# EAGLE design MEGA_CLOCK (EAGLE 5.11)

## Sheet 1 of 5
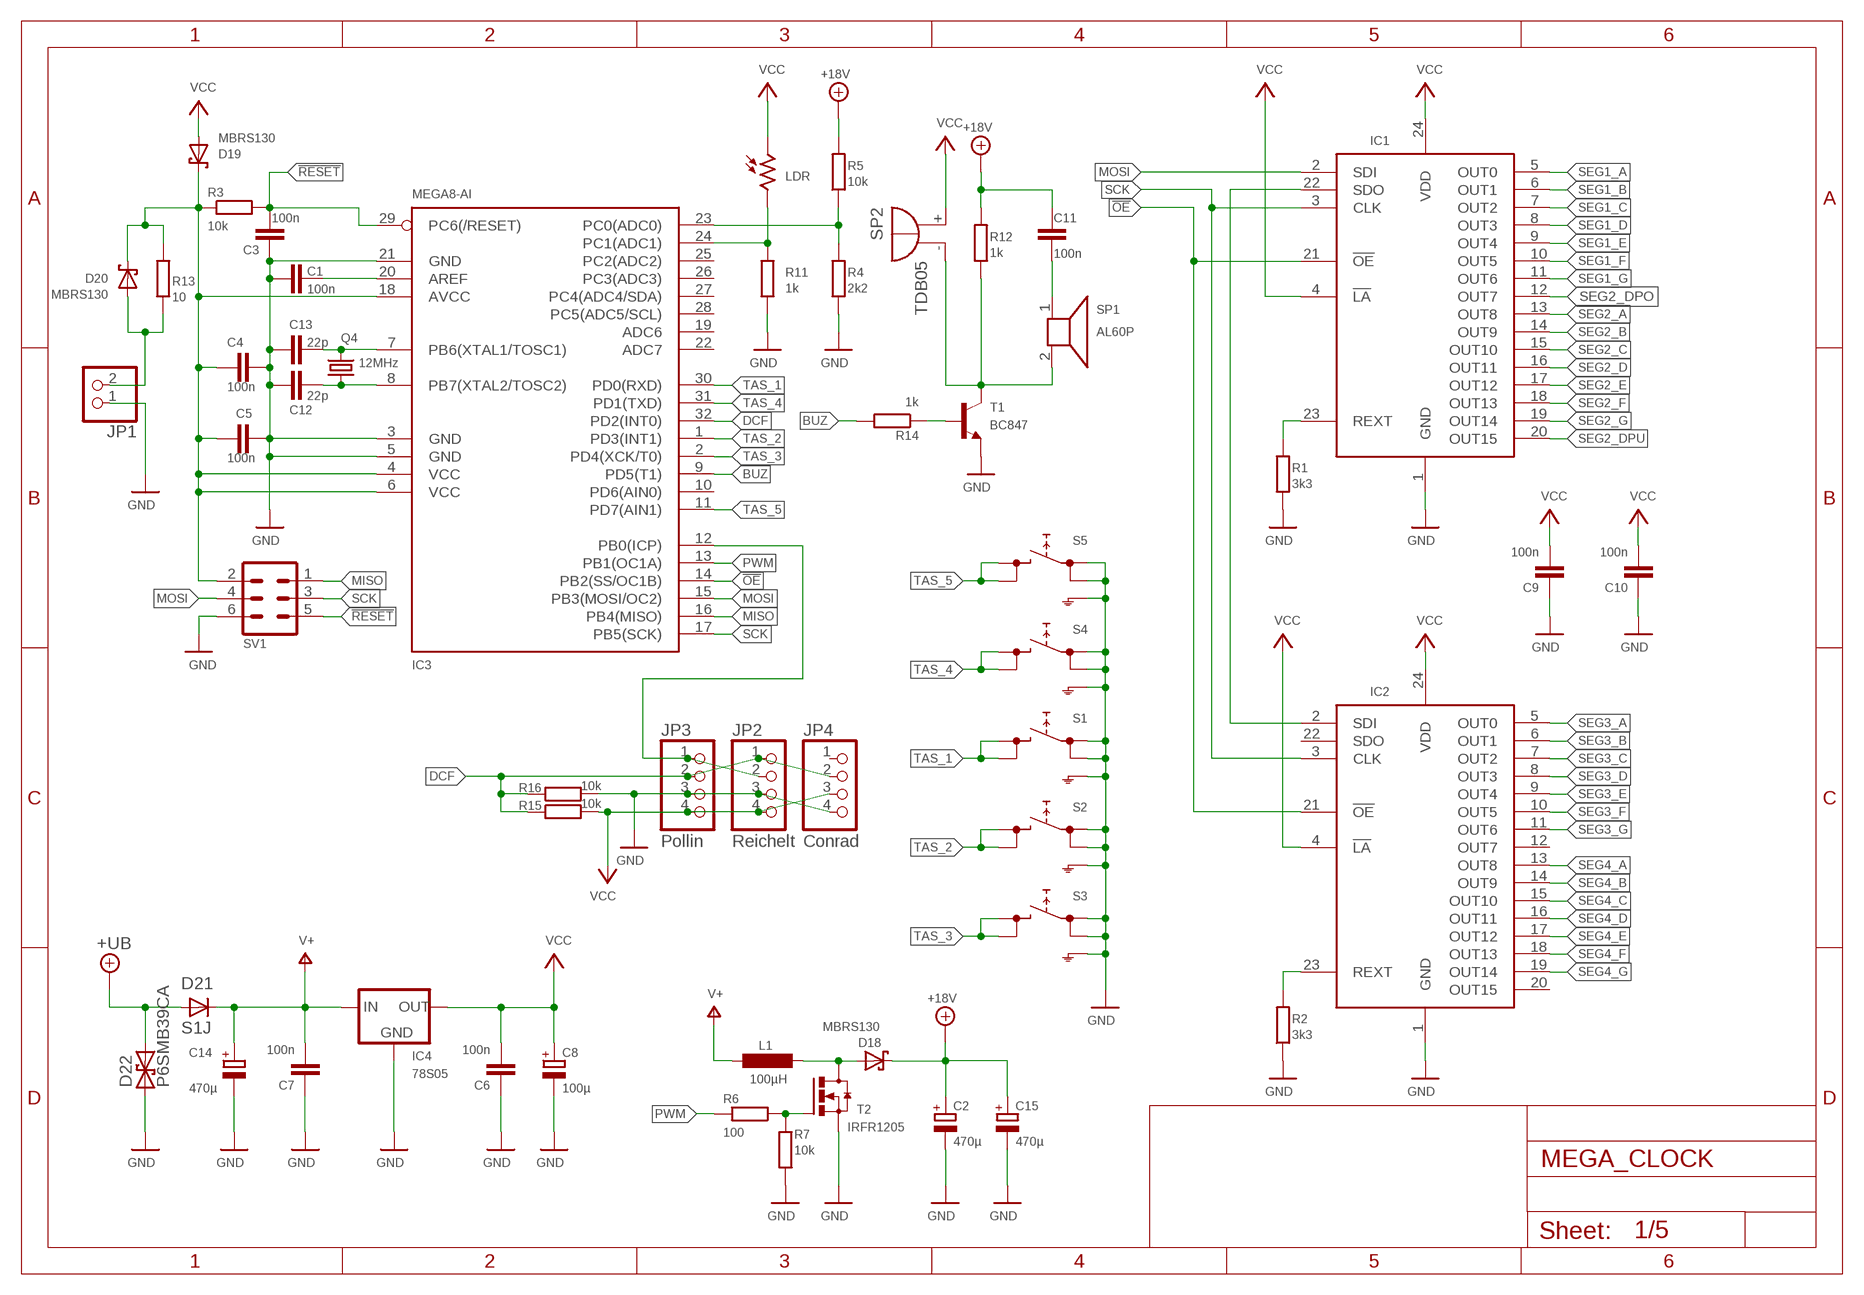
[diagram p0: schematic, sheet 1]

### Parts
C1  100n  C-EUC0805  [C0805]
C2  470µ  CPOL-EUE5-10.5  [E5-10,5]
C3  100n  C-EUC0805  [C0805]
C4  100n  C-EUC0805  [C0805]
C5  100n  C-EUC0805  [C0805]
C6  100n  C-EUC0805  [C0805]
C7  100n  C-EUC0805  [C0805]
C8  100µ  CPOL-EUSMCD  [SMC_D]
C9  100n  C-EUC0805  [C0805]
C10  100n  C-EUC0805  [C0805]
C11  100n  C-EUC0805  [C0805]
C12  22p  C-EUC0805  [C0805]
C13  22p  C-EUC0805  [C0805]
C14  470µ  CPOL-EUE5-10.5  [E5-10,5]
C15  470µ  CPOL-EUE5-10.5  [E5-10,5]
D18  MBRS130  MBRS130LT3  [SMB]
D19  MBRS130  MBRS130LT3  [SMB]
D20  MBRS130  MBRS130LT3  [SMB]
D21  S1J  GF1  [SMA-DO214AC]
D22  P6SMB39CA  [DO214AC-BI]
IC1  SCT24  [SSOP24]
IC2  SCT24  [SSOP24]
IC3  MEGA8-AI  [TQFP32-08]
IC4  78S05  78XXS  [78XXS]
JP1  PINHD-1X2  [1X02]
JP2  Reichelt  PINHD-1X4/90  [1X04/90]
JP3  Pollin  PINHD-1X4/90  [1X04/90]
JP4  Conrad  PINHD-1X4/90  [1X04/90]
L1  100µH  DO3316P  [DO3316P]
LDR  A1050_09  [T0-46-A10XX]
Q4  12MHz  CRYSTALCTS406  [CTS406]
R1  3k3  R-EU_R0805  [R0805]
R2  3k3  R-EU_R0805  [R0805]
R3  10k  R-EU_R0805  [R0805]
R4  2k2  R-EU_R0805  [R0805]
R5  10k  R-EU_R0805  [R0805]
R6  100  R-EU_R0805  [R0805]
R7  10k  R-EU_R0805  [R0805]
R11  1k  R-EU_R0805  [R0805]
R12  1k  R-EU_R0805  [R0805]
R13  10  R-EU_R0805  [R0805]
R14  1k  R-EU_R0805  [R0805]
R15  10k  R-EU_R0805  [R0805]
R16  10k  R-EU_R0805  [R0805]
S1  SKHMPWE010  [SKHMPXE010]
S2  SKHMPWE010  [SKHMPXE010]
S3  SKHMPWE010  [SKHMPXE010]
S4  SKHMPWE010  [SKHMPXE010]
S5  SKHMPWE010  [SKHMPXE010]
SP1  AL60P  [AL60P]
SP2  TDB05  BMT1205XH7.5  [BMT1205XH7.5]
SV1  ML6  [ML6]
T1  BC847  [SOT23]
T2  IRFR1205  [D-PAK_TO252AA]

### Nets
!OE: IC1.21(!OE) IC2.21(!OE) IC3.14(PB2(SS/OC1B))
!RESET: C3.2 IC3.29(PC6(/RESET)) R3.2 SV1.5
+12V: C2.+ C11.2 C15.+ D18.C R5.2 R12.2 ; supply symbol labelled +18V ; also sheet 2,3,4,5
+UB: D21.A D22.2
BUZ: IC3.9(PD5(T1)) R14.2
DCF: IC3.32(PD2(INT0)) JP2.1 JP3.2 JP4.2 R15.1 R16.1
GND: C1.1 C2.- C3.1 C4.2 C5.2 C6.1 C7.1 C8.- C9.1 C10.1 C12.1 C13.1 C14.- C15.- D22.1 IC1.1(GND) IC2.1(GND) IC3.3(GND) IC3.5(GND) IC3.21(GND) IC4.GND JP1.1 JP2.3 JP3.3 JP4.4 R1.1 R2.1 R4.1 R7.2 R11.1 R16.2 S1.1(1.1) S1.2(1.2) S1.5(SH) S2.1(1.1) S2.2(1.2) S2.5(SH) S3.1(1.1) S3.2(1.2) S3.5(SH) S4.1(1.1) S4.2(1.2) S4.5(SH) S5.1(1.1) S5.2(1.2) S5.5(SH) SV1.6 T1.2(E) T2.3(S)
MISO: IC3.16(PB4(MISO)) SV1.1
MOSI: IC1.2(SDI) IC3.15(PB3(MOSI/OC2)) SV1.4
N$2: IC2.23(REXT) R2.2
N$3: IC1.23(REXT) R1.2
N$5: C1.2 IC3.20(AREF)
N$6: IC3.23(PC0(ADC0)) R4.2 R5.1
N$7: C13.2 IC3.7(PB6(XTAL1/TOSC1)) Q4.3
N$8: C12.2 IC3.8(PB7(XTAL2/TOSC2)) Q4.1
N$9: D18.A L1.2 T2.4(D)
N$10: IC3.24(PC1(ADC1)) LDR.2 R11.2
N$11: R6.1 R7.1 T2.1(G)
N$13: R12.1 SP1.2 SP2.- T1.3(C)
N$31: C11.1 SP1.1
N$36: D20.A JP1.2 R13.1
N$41: R14.1 T1.1(B)
N$46: C4.1 C5.1 D19.C D20.C IC3.4(VCC) IC3.6(VCC) IC3.18(AVCC) R3.1 R13.2 SV1.2
N$83: IC3.12(PB0(ICP)) JP2.2 JP3.1
N$101: IC1.22(SDO) IC2.2(SDI)
PWM: IC3.13(PB1(OC1A)) R6.2
SCK: IC1.3(CLK) IC2.3(CLK) IC3.17(PB5(SCK)) SV1.3
SEG1_A: IC1.5(OUT0) ; also sheet 2
SEG1_B: IC1.6(OUT1) ; also sheet 2
SEG1_C: IC1.7(OUT2) ; also sheet 2
SEG1_D: IC1.8(OUT3) ; also sheet 2
SEG1_E: IC1.9(OUT4) ; also sheet 2
SEG1_F: IC1.10(OUT5) ; also sheet 2
SEG1_G: IC1.11(OUT6) ; also sheet 2
SEG2_A: IC1.13(OUT8) ; also sheet 3
SEG2_B: IC1.14(OUT9) ; also sheet 3
SEG2_C: IC1.15(OUT10) ; also sheet 3
SEG2_D: IC1.16(OUT11) ; also sheet 3
SEG2_DPO: IC1.12(OUT7) ; also sheet 3
SEG2_DPU: IC1.20(OUT15) ; also sheet 3
SEG2_E: IC1.17(OUT12) ; also sheet 3
SEG2_F: IC1.18(OUT13) ; also sheet 3
SEG2_G: IC1.19(OUT14) ; also sheet 3
SEG3_A: IC2.5(OUT0) ; also sheet 4
SEG3_B: IC2.6(OUT1) ; also sheet 4
SEG3_C: IC2.7(OUT2) ; also sheet 4
SEG3_D: IC2.8(OUT3) ; also sheet 4
SEG3_E: IC2.9(OUT4) ; also sheet 4
SEG3_F: IC2.10(OUT5) ; also sheet 4
SEG3_G: IC2.11(OUT6) ; also sheet 4
SEG4_A: IC2.13(OUT8) ; also sheet 5
SEG4_B: IC2.14(OUT9) ; also sheet 5
SEG4_C: IC2.15(OUT10) ; also sheet 5
SEG4_D: IC2.16(OUT11) ; also sheet 5
SEG4_E: IC2.17(OUT12) ; also sheet 5
SEG4_F: IC2.18(OUT13) ; also sheet 5
SEG4_G: IC2.19(OUT14) ; also sheet 5
TAS_1: IC3.30(PD0(RXD)) S1.3(2.1) S1.4(2.2)
TAS_2: IC3.1(PD3(INT1)) S2.3(2.1) S2.4(2.2)
TAS_3: IC3.2(PD4(XCK/T0)) S3.3(2.1) S3.4(2.2)
TAS_4: IC3.31(PD1(TXD)) S4.3(2.1) S4.4(2.2)
TAS_5: IC3.11(PD7(AIN1)) S5.3(2.1) S5.4(2.2)
V+: C7.2 C14.+ D21.K(C) IC4.IN L1.1
VCC: C6.2 C8.+ C9.2 C10.2 D19.A IC1.4(!LA) IC1.24(VDD) IC2.4(!LA) IC2.24(VDD) IC4.OUT JP2.4 JP3.4 JP4.3 LDR.1 R15.2 SP2.+
Unconnected: IC2.12(OUT7) IC2.20(OUT15) IC2.22(SDO) IC3.10(PD6(AIN0)) IC3.19(ADC6) IC3.22(ADC7) IC3.25(PC2(ADC2)) IC3.26(PC3(ADC3)) IC3.27(PC4(ADC4/SDA)) IC3.28(PC5(ADC5/SCL)) JP4.1

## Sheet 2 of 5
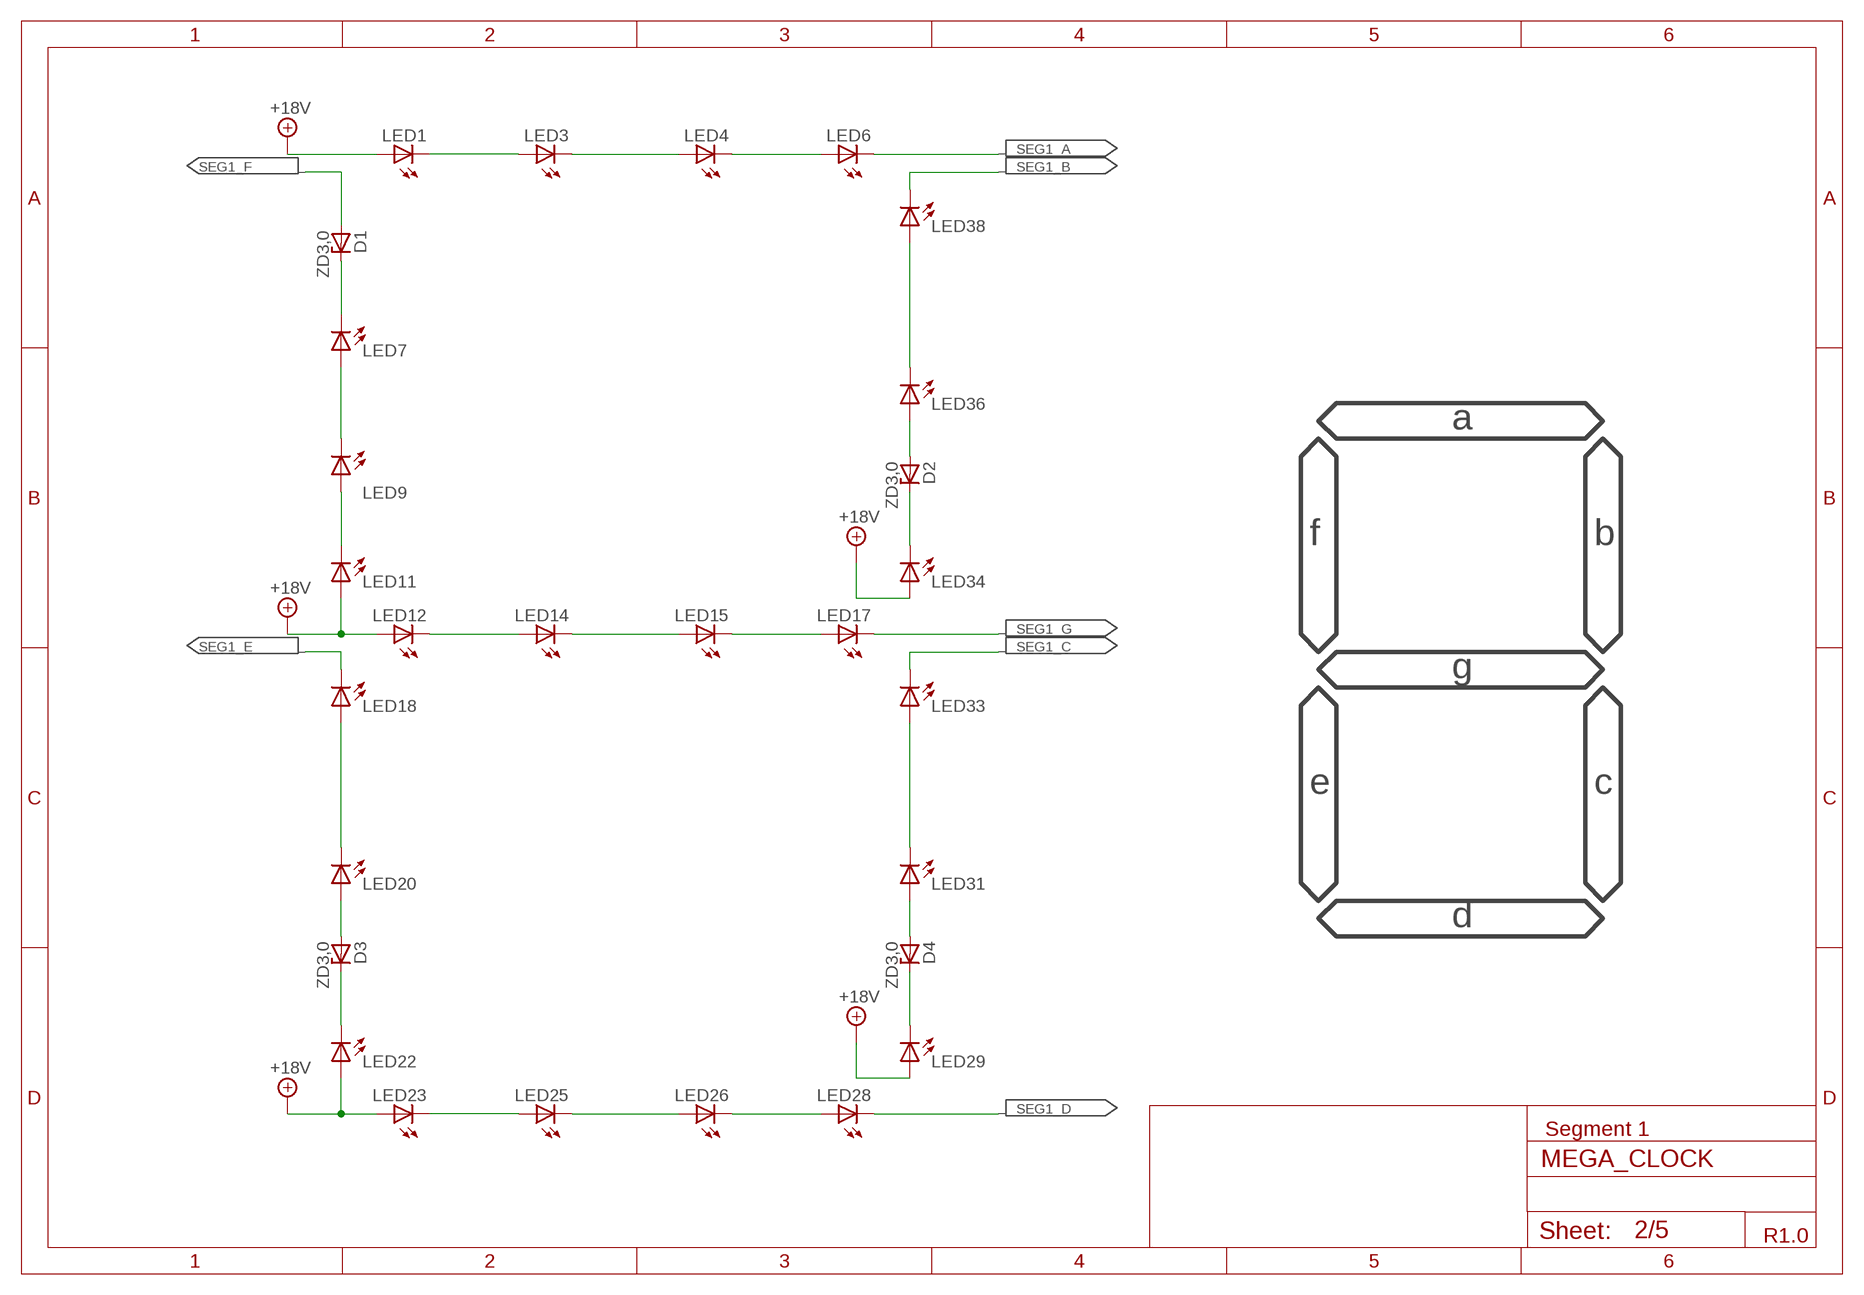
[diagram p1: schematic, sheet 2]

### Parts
D1  ZD3,0  ZENER-DIODESOD80C  [SOD80C]
D2  ZD3,0  ZENER-DIODESOD80C  [SOD80C]
D3  ZD3,0  ZENER-DIODESOD80C  [SOD80C]
D4  ZD3,0  ZENER-DIODESOD80C  [SOD80C]
LED1  LEDP-LCC-2  [P-LCC-2]
LED3  LEDP-LCC-2  [P-LCC-2]
LED4  LEDP-LCC-2  [P-LCC-2]
LED6  LEDP-LCC-2  [P-LCC-2]
LED7  LEDP-LCC-2  [P-LCC-2]
LED9  LEDP-LCC-2  [P-LCC-2]
LED11  LEDP-LCC-2  [P-LCC-2]
LED12  LEDP-LCC-2  [P-LCC-2]
LED14  LEDP-LCC-2  [P-LCC-2]
LED15  LEDP-LCC-2  [P-LCC-2]
LED17  LEDP-LCC-2  [P-LCC-2]
LED18  LEDP-LCC-2  [P-LCC-2]
LED20  LEDP-LCC-2  [P-LCC-2]
LED22  LEDP-LCC-2  [P-LCC-2]
LED23  LEDP-LCC-2  [P-LCC-2]
LED25  LEDP-LCC-2  [P-LCC-2]
LED26  LEDP-LCC-2  [P-LCC-2]
LED28  LEDP-LCC-2  [P-LCC-2]
LED29  LEDP-LCC-2  [P-LCC-2]
LED31  LEDP-LCC-2  [P-LCC-2]
LED33  LEDP-LCC-2  [P-LCC-2]
LED34  LEDP-LCC-2  [P-LCC-2]
LED36  LEDP-LCC-2  [P-LCC-2]
LED38  LEDP-LCC-2  [P-LCC-2]

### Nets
+12V: LED1.A LED11.A LED12.A LED22.A LED23.A LED29.A LED34.A ; supply symbol labelled +18V ; also sheet 1,3,4,5
N$14: LED18.A LED20.C
N$15: LED23.C LED25.A
N$16: LED3.C LED4.A
N$17: LED26.C LED28.A
N$18: LED15.C LED17.A
N$19: LED12.C LED14.A
N$20: LED1.C LED3.A
N$21: LED14.C LED15.A
N$22: LED4.C LED6.A
N$23: LED7.A LED9.C
N$24: D3.A LED20.A
N$25: LED36.C LED38.A
N$26: LED25.C LED26.A
N$27: D3.C LED22.C
N$28: LED31.C LED33.A
N$39: D4.C LED29.C
N$44: D4.A LED31.A
N$76: D1.C LED7.C
N$82: LED9.A LED11.C
N$107: D2.C LED34.C
N$108: D2.A LED36.A
SEG1_A: LED6.C ; also sheet 1
SEG1_B: LED38.C ; also sheet 1
SEG1_C: LED33.C ; also sheet 1
SEG1_D: LED28.C ; also sheet 1
SEG1_E: LED18.C ; also sheet 1
SEG1_F: D1.A ; also sheet 1
SEG1_G: LED17.C ; also sheet 1

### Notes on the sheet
- a
- f | b
- g
- e | c
- d
- Segment 1
- R1.0

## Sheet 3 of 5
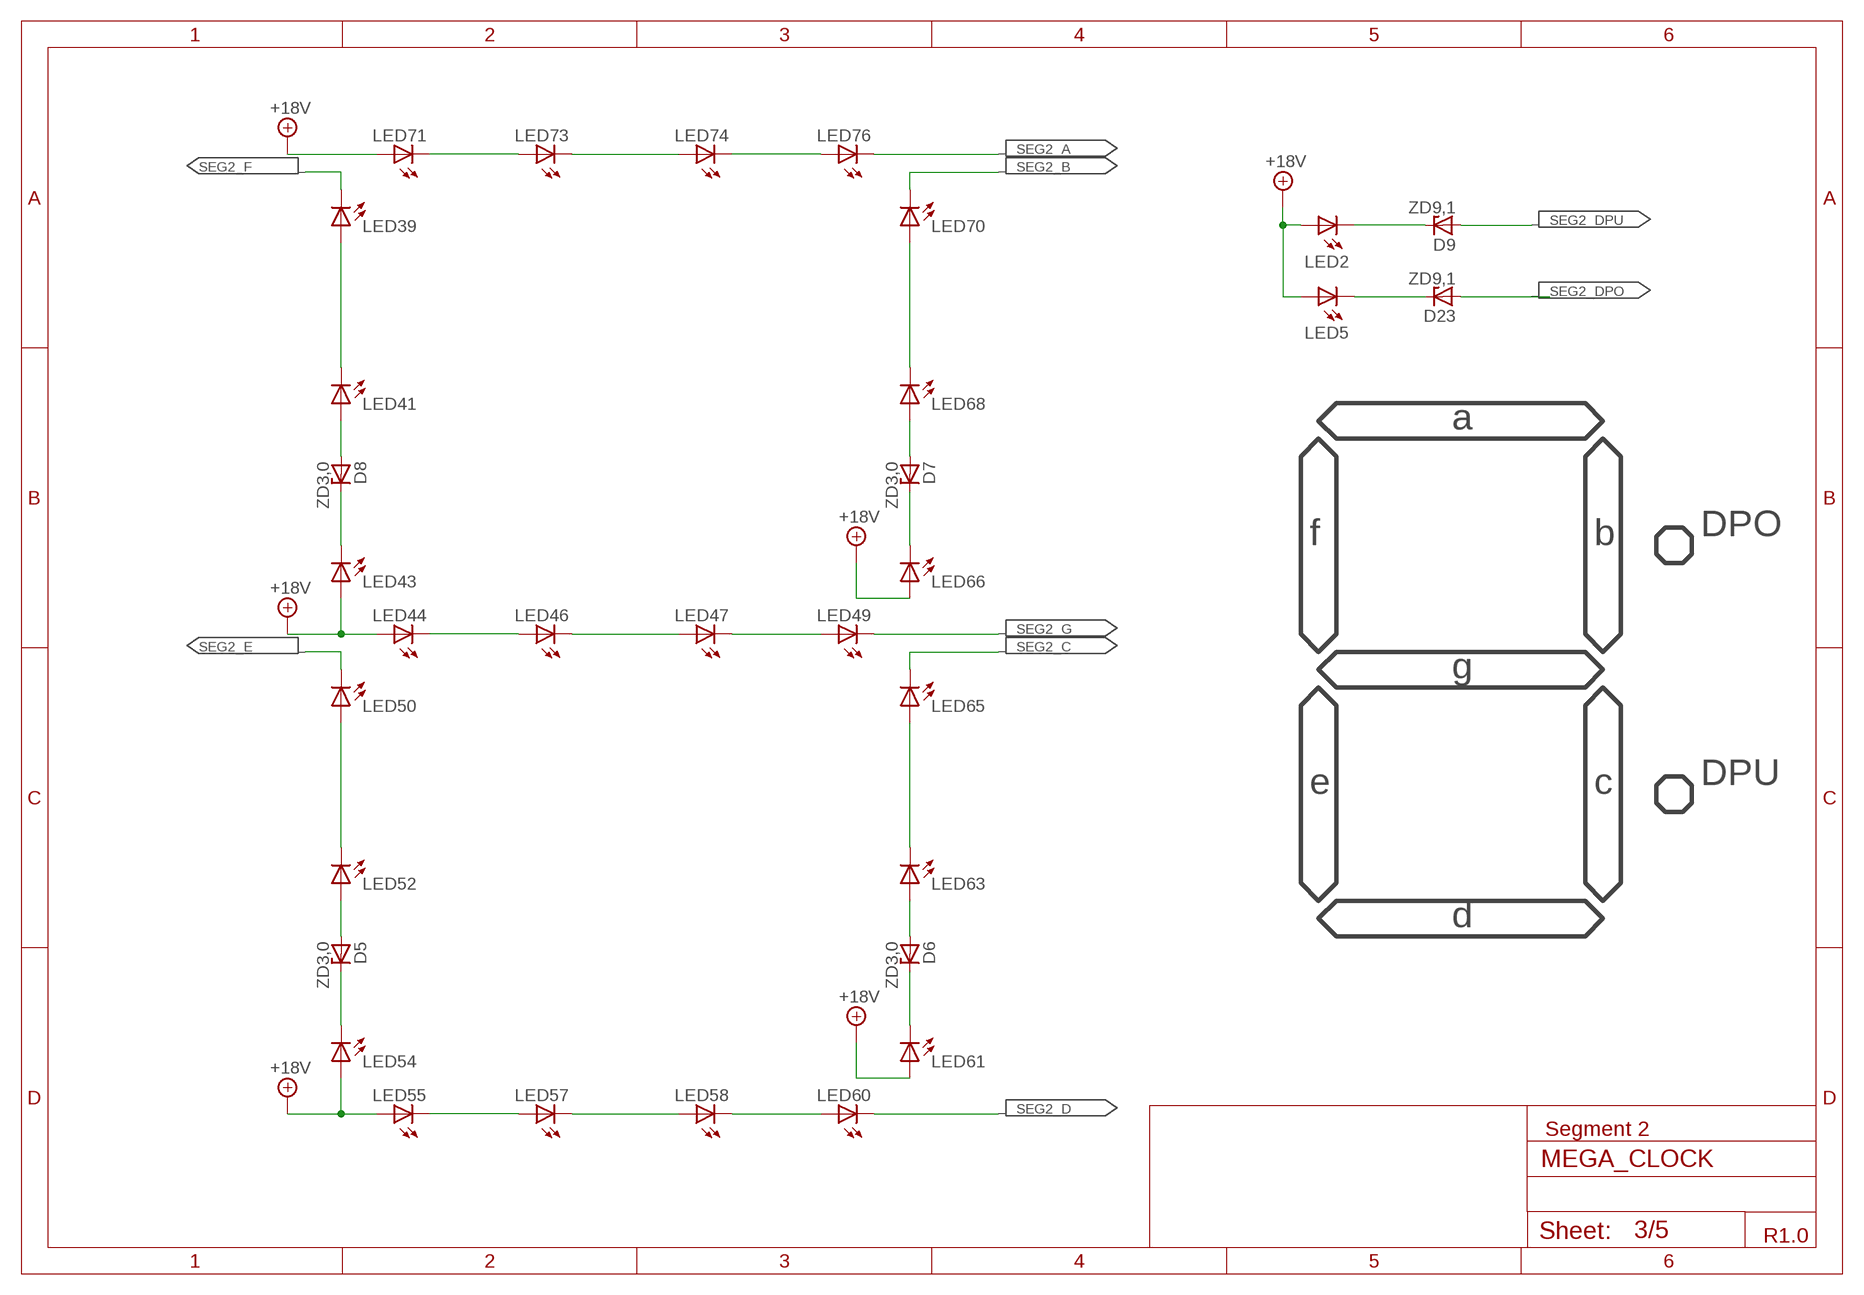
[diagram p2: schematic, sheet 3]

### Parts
D5  ZD3,0  ZENER-DIODESOD80C  [SOD80C]
D6  ZD3,0  ZENER-DIODESOD80C  [SOD80C]
D7  ZD3,0  ZENER-DIODESOD80C  [SOD80C]
D8  ZD3,0  ZENER-DIODESOD80C  [SOD80C]
D9  ZD9,1  ZENER-DIODESOD80C  [SOD80C]
D23  ZD9,1  ZENER-DIODESOD80C  [SOD80C]
LED2  LEDP-LCC-2  [P-LCC-2]
LED5  LEDP-LCC-2  [P-LCC-2]
LED39  LEDP-LCC-2  [P-LCC-2]
LED41  LEDP-LCC-2  [P-LCC-2]
LED43  LEDP-LCC-2  [P-LCC-2]
LED44  LEDP-LCC-2  [P-LCC-2]
LED46  LEDP-LCC-2  [P-LCC-2]
LED47  LEDP-LCC-2  [P-LCC-2]
LED49  LEDP-LCC-2  [P-LCC-2]
LED50  LEDP-LCC-2  [P-LCC-2]
LED52  LEDP-LCC-2  [P-LCC-2]
LED54  LEDP-LCC-2  [P-LCC-2]
LED55  LEDP-LCC-2  [P-LCC-2]
LED57  LEDP-LCC-2  [P-LCC-2]
LED58  LEDP-LCC-2  [P-LCC-2]
LED60  LEDP-LCC-2  [P-LCC-2]
LED61  LEDP-LCC-2  [P-LCC-2]
LED63  LEDP-LCC-2  [P-LCC-2]
LED65  LEDP-LCC-2  [P-LCC-2]
LED66  LEDP-LCC-2  [P-LCC-2]
LED68  LEDP-LCC-2  [P-LCC-2]
LED70  LEDP-LCC-2  [P-LCC-2]
LED71  LEDP-LCC-2  [P-LCC-2]
LED73  LEDP-LCC-2  [P-LCC-2]
LED74  LEDP-LCC-2  [P-LCC-2]
LED76  LEDP-LCC-2  [P-LCC-2]

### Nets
+12V: LED2.A LED5.A LED43.A LED44.A LED54.A LED55.A LED61.A LED66.A LED71.A ; supply symbol labelled +18V ; also sheet 1,2,4,5
N$1: D23.C LED5.C
N$29: LED39.A LED41.C
N$30: LED68.C LED70.A
N$32: LED74.C LED76.A
N$33: LED71.C LED73.A
N$34: LED47.C LED49.A
N$35: LED44.C LED46.A
N$37: D9.C LED2.C
N$38: D5.A LED52.A
N$40: LED58.C LED60.A
N$42: LED55.C LED57.A
N$43: D5.C LED54.C
N$45: D6.C LED61.C
N$47: LED50.A LED52.C
N$48: LED63.C LED65.A
N$51: LED73.C LED74.A
N$56: LED46.C LED47.A
N$61: LED57.C LED58.A
N$111: D6.A LED63.A
N$112: D8.A LED41.A
N$113: D8.C LED43.C
N$114: D7.C LED66.C
N$115: D7.A LED68.A
SEG2_A: LED76.C ; also sheet 1
SEG2_B: LED70.C ; also sheet 1
SEG2_C: LED65.C ; also sheet 1
SEG2_D: LED60.C ; also sheet 1
SEG2_DPO: D23.A ; also sheet 1
SEG2_DPU: D9.A ; also sheet 1
SEG2_E: LED50.C ; also sheet 1
SEG2_F: LED39.C ; also sheet 1
SEG2_G: LED49.C ; also sheet 1

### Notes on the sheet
- a
- f | b | DPO
- g
- e | c | DPU
- d
- Segment 2
- R1.0

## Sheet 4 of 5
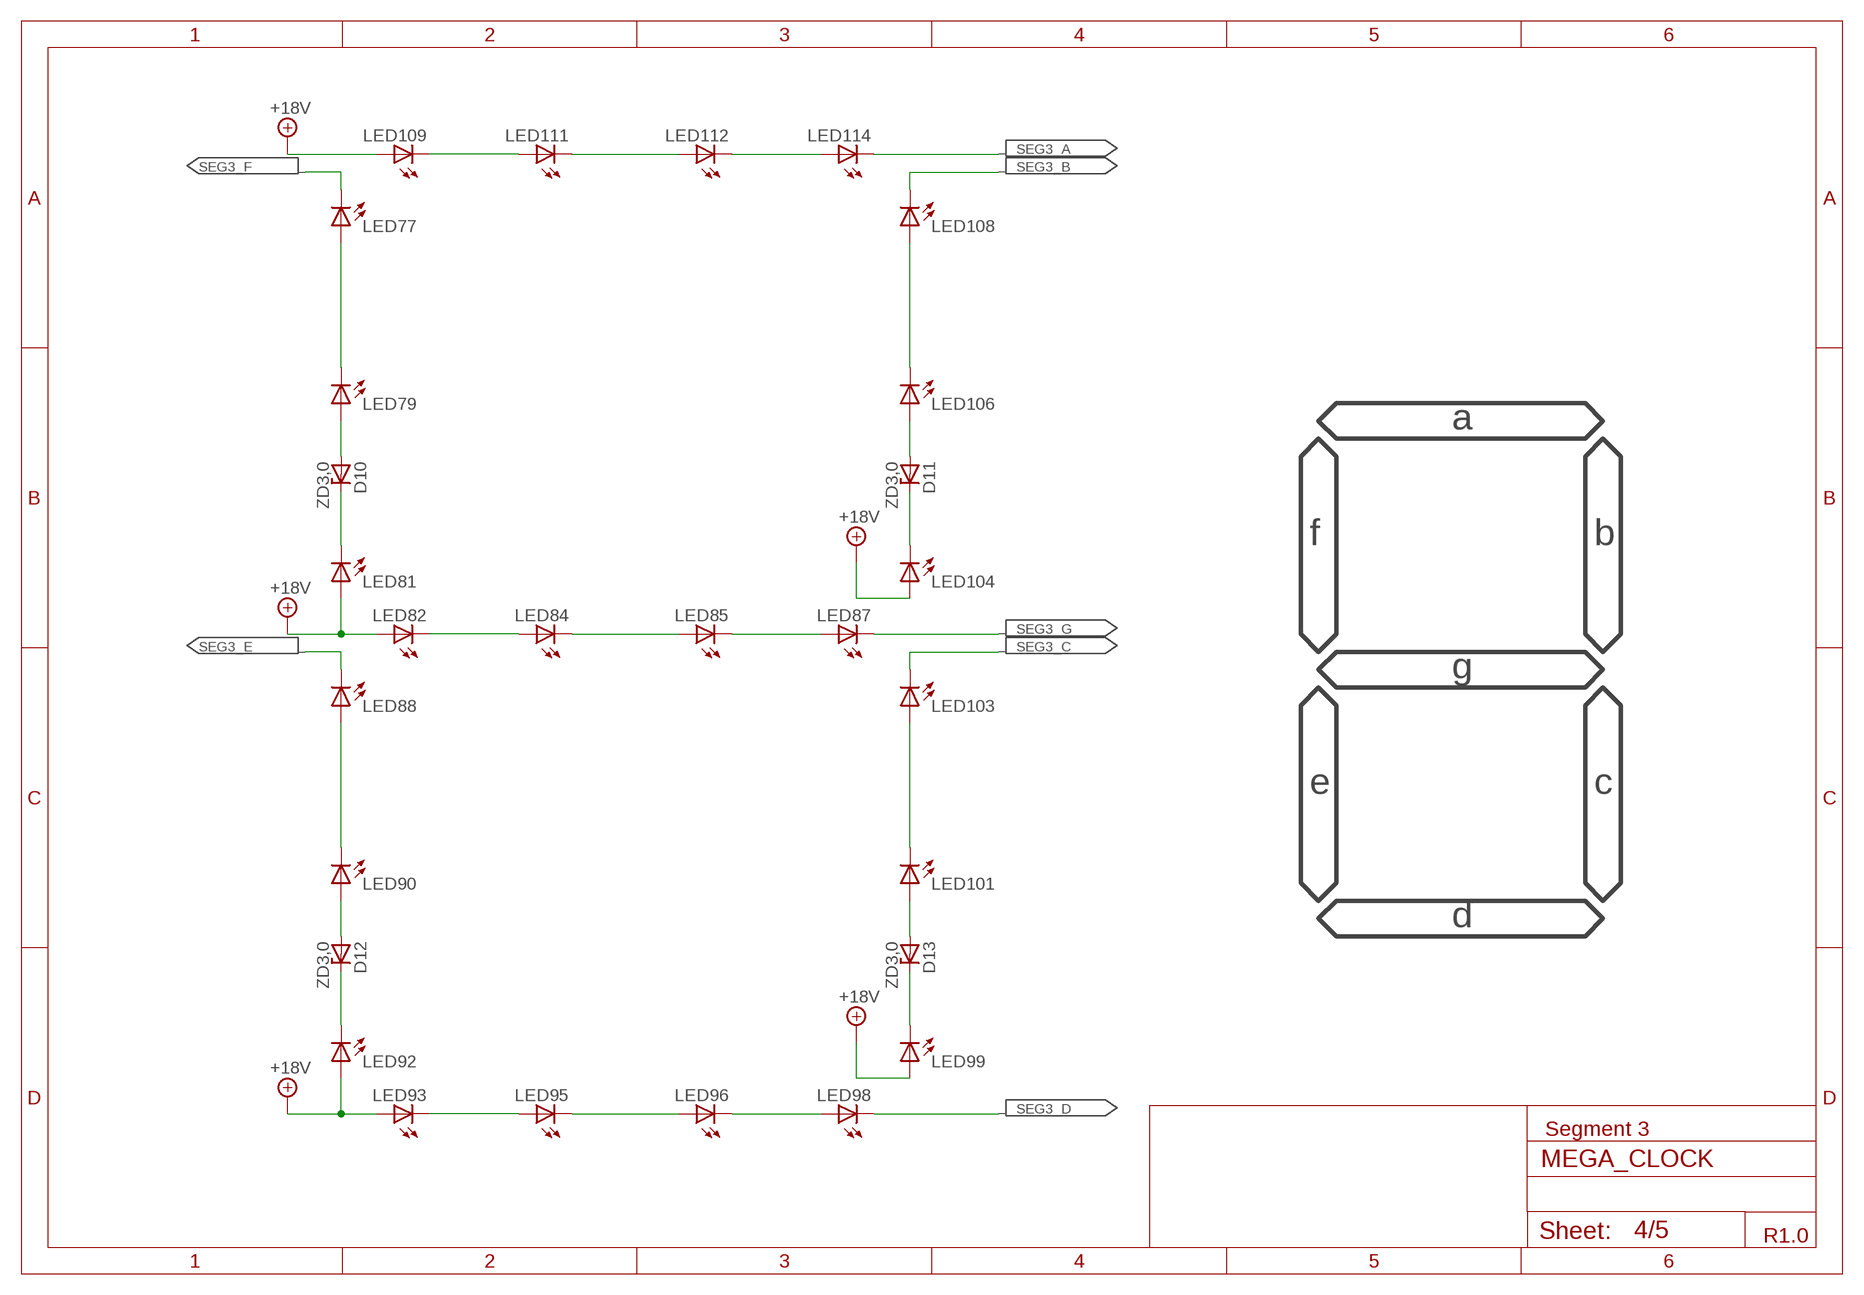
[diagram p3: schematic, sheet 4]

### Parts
D10  ZD3,0  ZENER-DIODESOD80C  [SOD80C]
D11  ZD3,0  ZENER-DIODESOD80C  [SOD80C]
D12  ZD3,0  ZENER-DIODESOD80C  [SOD80C]
D13  ZD3,0  ZENER-DIODESOD80C  [SOD80C]
LED77  LEDP-LCC-2  [P-LCC-2]
LED79  LEDP-LCC-2  [P-LCC-2]
LED81  LEDP-LCC-2  [P-LCC-2]
LED82  LEDP-LCC-2  [P-LCC-2]
LED84  LEDP-LCC-2  [P-LCC-2]
LED85  LEDP-LCC-2  [P-LCC-2]
LED87  LEDP-LCC-2  [P-LCC-2]
LED88  LEDP-LCC-2  [P-LCC-2]
LED90  LEDP-LCC-2  [P-LCC-2]
LED92  LEDP-LCC-2  [P-LCC-2]
LED93  LEDP-LCC-2  [P-LCC-2]
LED95  LEDP-LCC-2  [P-LCC-2]
LED96  LEDP-LCC-2  [P-LCC-2]
LED98  LEDP-LCC-2  [P-LCC-2]
LED99  LEDP-LCC-2  [P-LCC-2]
LED101  LEDP-LCC-2  [P-LCC-2]
LED103  LEDP-LCC-2  [P-LCC-2]
LED104  LEDP-LCC-2  [P-LCC-2]
LED106  LEDP-LCC-2  [P-LCC-2]
LED108  LEDP-LCC-2  [P-LCC-2]
LED109  LEDP-LCC-2  [P-LCC-2]
LED111  LEDP-LCC-2  [P-LCC-2]
LED112  LEDP-LCC-2  [P-LCC-2]
LED114  LEDP-LCC-2  [P-LCC-2]

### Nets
+12V: LED81.A LED82.A LED92.A LED93.A LED99.A LED104.A LED109.A ; supply symbol labelled +18V ; also sheet 1,2,3,5
N$49: LED96.C LED98.A
N$50: LED93.C LED95.A
N$52: D10.C LED81.C
N$53: D10.A LED79.A
N$54: LED85.C LED87.A
N$55: LED82.C LED84.A
N$57: LED88.A LED90.C
N$58: LED101.C LED103.A
N$59: LED109.C LED111.A
N$60: LED112.C LED114.A
N$62: LED77.A LED79.C
N$63: LED106.C LED108.A
N$86: LED111.C LED112.A
N$91: LED84.C LED85.A
N$96: LED95.C LED96.A
N$99: D11.A LED106.A
N$104: D11.C LED104.C
N$116: D13.A LED101.A
N$117: D13.C LED99.C
N$118: D12.A LED90.A
N$119: D12.C LED92.C
SEG3_A: LED114.C ; also sheet 1
SEG3_B: LED108.C ; also sheet 1
SEG3_C: LED103.C ; also sheet 1
SEG3_D: LED98.C ; also sheet 1
SEG3_E: LED88.C ; also sheet 1
SEG3_F: LED77.C ; also sheet 1
SEG3_G: LED87.C ; also sheet 1

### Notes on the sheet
- a
- f | b
- g
- e | c
- d
- Segment 3
- R1.0

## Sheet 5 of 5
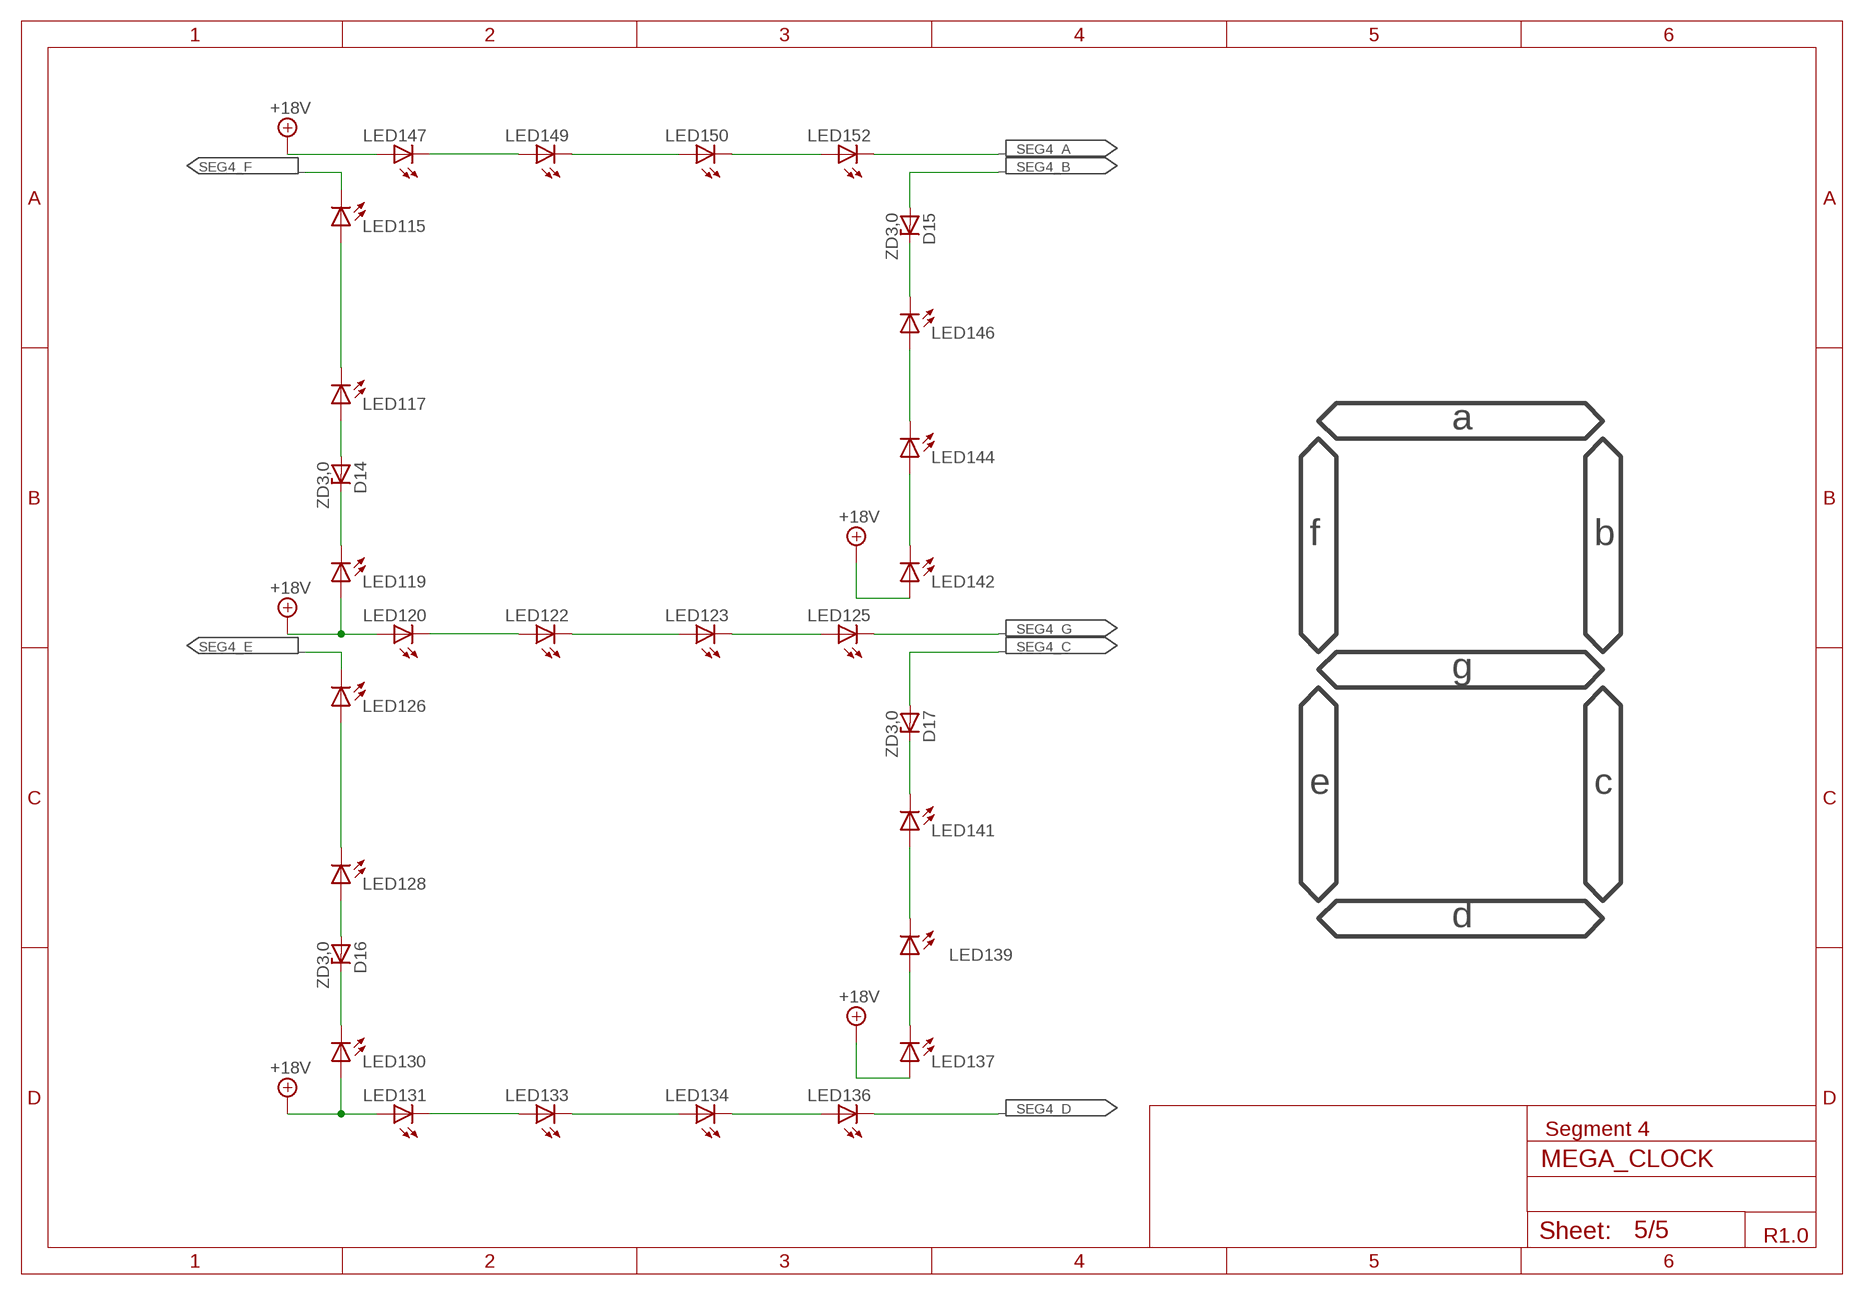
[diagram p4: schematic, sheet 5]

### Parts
D14  ZD3,0  ZENER-DIODESOD80C  [SOD80C]
D15  ZD3,0  ZENER-DIODESOD80C  [SOD80C]
D16  ZD3,0  ZENER-DIODESOD80C  [SOD80C]
D17  ZD3,0  ZENER-DIODESOD80C  [SOD80C]
LED115  LEDP-LCC-2  [P-LCC-2]
LED117  LEDP-LCC-2  [P-LCC-2]
LED119  LEDP-LCC-2  [P-LCC-2]
LED120  LEDP-LCC-2  [P-LCC-2]
LED122  LEDP-LCC-2  [P-LCC-2]
LED123  LEDP-LCC-2  [P-LCC-2]
LED125  LEDP-LCC-2  [P-LCC-2]
LED126  LEDP-LCC-2  [P-LCC-2]
LED128  LEDP-LCC-2  [P-LCC-2]
LED130  LEDP-LCC-2  [P-LCC-2]
LED131  LEDP-LCC-2  [P-LCC-2]
LED133  LEDP-LCC-2  [P-LCC-2]
LED134  LEDP-LCC-2  [P-LCC-2]
LED136  LEDP-LCC-2  [P-LCC-2]
LED137  LEDP-LCC-2  [P-LCC-2]
LED139  LEDP-LCC-2  [P-LCC-2]
LED141  LEDP-LCC-2  [P-LCC-2]
LED142  LEDP-LCC-2  [P-LCC-2]
LED144  LEDP-LCC-2  [P-LCC-2]
LED146  LEDP-LCC-2  [P-LCC-2]
LED147  LEDP-LCC-2  [P-LCC-2]
LED149  LEDP-LCC-2  [P-LCC-2]
LED150  LEDP-LCC-2  [P-LCC-2]
LED152  LEDP-LCC-2  [P-LCC-2]

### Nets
+12V: LED119.A LED120.A LED130.A LED131.A LED137.A LED142.A LED147.A ; supply symbol labelled +18V ; also sheet 1,2,3,4
N$12: LED142.C LED144.A
N$64: LED134.C LED136.A
N$65: LED131.C LED133.A
N$66: D15.C LED146.C
N$67: D14.A LED117.A
N$68: LED139.C LED141.A
N$69: D14.C LED119.C
N$70: LED126.A LED128.C
N$71: LED137.C LED139.A
N$72: D17.C LED141.C
N$74: LED150.C LED152.A
N$75: LED147.C LED149.A
N$77: LED115.A LED117.C
N$78: LED144.C LED146.A
N$79: LED123.C LED125.A
N$80: LED120.C LED122.A
N$120: D16.A LED128.A
N$121: LED149.C LED150.A
N$122: D16.C LED130.C
N$126: LED122.C LED123.A
N$131: LED133.C LED134.A
SEG4_A: LED152.C ; also sheet 1
SEG4_B: D15.A ; also sheet 1
SEG4_C: D17.A ; also sheet 1
SEG4_D: LED136.C ; also sheet 1
SEG4_E: LED126.C ; also sheet 1
SEG4_F: LED115.C ; also sheet 1
SEG4_G: LED125.C ; also sheet 1

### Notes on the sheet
- a
- f | b
- g
- e | c
- d
- Segment 4
- R1.0

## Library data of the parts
C1 C3-C7 C9-C13 = rcl:C-EU: CAPACITOR, European symbol
C2 C8 C14 C15 = rcl:CPOL-EU: POLARIZED CAPACITOR, European symbol
D1-D17 D23 = diode:ZENER-DIODE: Z-Diode
D18-D20 = diode:MBRS130LT3: Schottky Power Rectifier
D21 = diode:GF1: DIODE
D22 = diode:P6SMB39CA
IC1 IC2 = StarChips:SCT24
IC3 = atmel:MEGA8: MICROCONTROLLER 8 Kbytes FLASH, 1 kbytes SRAM, 512 bytes EEPROM, USART, 6-channel 10 bit ADC, 2-channel 8 bit ADC Pin compatible with Atmega48, ATMega88, ATMega168 Source: avr.lbr
IC4 = v-reg:78XXS: VOLTAGE REGULATOR
JP1 = pinhead:PINHD-1X2: PIN HEADER
JP2-JP4 = pinhead:PINHD-1X4: PIN HEADER
L1 = inductor-coilcraft:DO3316P: COILCRAFT; OC_FARNELL: unknown; OC_NEWARK: unknown
LDR = photo-elements:A10: Sensor Robust Light Sensing Applications
LED1-LED7 LED9 LED11 LED12 LED14 LED15 LED17 LED18 LED20 LED22 LED23 LED25 LED26 LED28 LED29 LED31 LED33 LED34 LED36 LED38 LED39 LED41 LED43 LED44 LED46 LED47 LED49 LED50 LED52 LED54 LED55 LED57 LED58 LED60 LED61 LED63 LED65 LED66 LED68 LED70 LED71 LED73 LED74 LED76 LED77 LED79 LED81 LED82 LED84 LED85 LED87 LED88 LED90 LED92 LED93 LED95 LED96 LED98 LED99 LED101 LED103 LED104 LED106 LED108 LED109 LED111 LED112 LED114 LED115 LED117 LED119 LED120 LED122 LED123 LED125 LED126 LED128 LED130 LED131 LED133 LED134 LED136 LED137 LED139 LED141 LED142 LED144 LED146 LED147 LED149 LED150 LED152 = led:LED: LED
Q4 = crystal:CRYSTAL: CRYSTAL
R1-R7 R11-R16 = rcl:R-EU_: RESISTOR, European symbol
S1-S5 = switch:SKHMP*E010: 6.2 X 6.5mm TACT Switch (SMD) Source: http://www3.alps.co.jp/WebObjects/catalog.woa/PDF/E/Switch/Tact/SKHM/SKHM.PDF
SP1 = buzzer:AL60P: SPEAKER; OC_FARNELL: unknown; OC_NEWARK: unknown
SP2 = buzzer:BMT1205XH7.5: MAGNETIC TRANSDUCER
SV1 = con-harting-ml:ML6: HARTING
T1 = transistor:BC847: NPN TRANSISTOR
T2 = transistor-power:IRFR1205

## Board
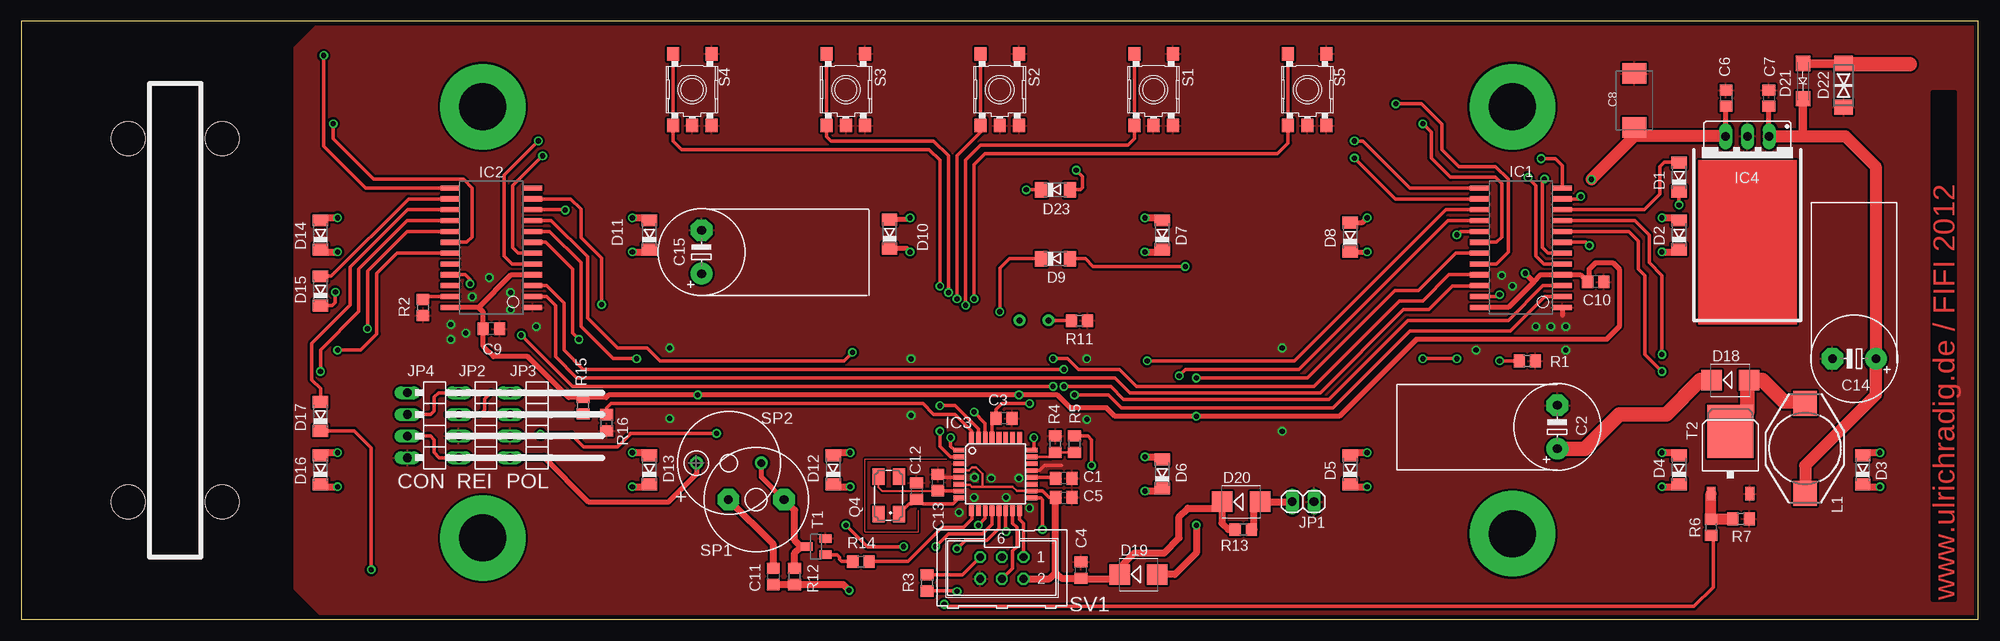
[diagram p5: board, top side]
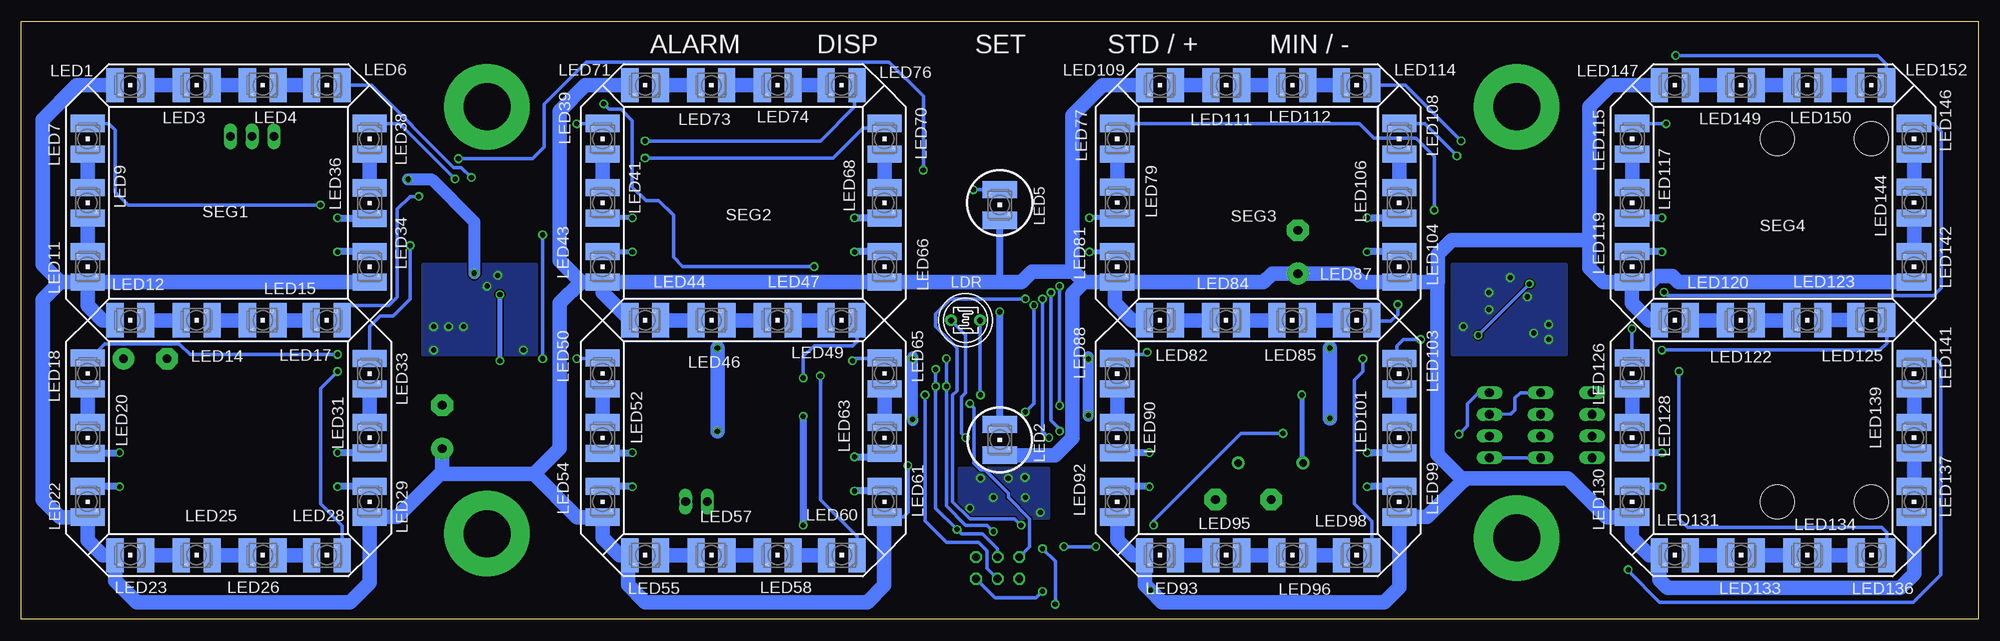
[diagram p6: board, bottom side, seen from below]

Size 229 x 70 mm. Coordinates in mm from the lower left corner, seen from the top.
Outline: 229,0 229,70 0,70 0,0 229,0
Copper layers (1*16): Top 0.035mm / dielectric 1.5mm / Bottom 0.035mm
Design rules "fifisdr": minimum track width 10mil, minimum drill 0.3mm, track to track 6mil, track to pad 6mil, pad to pad 6mil, via to via 6mil, smd to smd 6mil, copper to edge 20mil, drill to drill 8mil, minimum pad ring 7mil, minimum via ring 8mil, stop-mask expansion 4mil, vias tented up to drill 50mil, thermal gap 10mil
Holes 4 mm at 12.5,13.75 12.5,56.25 23.5,56.25 23.5,13.75

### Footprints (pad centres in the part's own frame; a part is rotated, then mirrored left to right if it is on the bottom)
C0805 = smd 1.3 x 1.5: 1 -0.95,0; 2 0.95,0
E5-10,5 = drill 1.016 pad 2.54 round: + -2.54,0 | drill 1.016 pad 2.54 octagon: - 2.54,0
SMC_D = smd 2.4 x 2.8: + -3.15,0; - 3.15,0
SOD80C = smd 1.4 x 1.8: A 1.7,0; C -1.7,0
SMB = smd 2.4 x 2.4: A 2.2,0; C -2.2,0
SMA-DO214AC = smd 1.8 x 1.7: A -2.05,0; K 2.05,0
DO214AC-BI = smd 1.8 x 2.2: 1 -2.55,0; 2 2.55,0
SSOP24 = smd 0.6 x 2.2: 1 -6.985,-4.854; 2 -5.715,-4.854; 3 -4.445,-4.854; 4 -3.175,-4.854; 5 -1.905,-4.854; 6 -0.635,-4.854; 7 0.635,-4.854; 8 1.905,-4.854; 9 3.175,-4.854; 10 4.445,-4.854; 11 5.715,-4.854; 12 6.985,-4.854; 13 6.985,4.854; 14 5.715,4.854; 15 4.445,4.854; 16 3.175,4.854; 17 1.905,4.854; 18 0.635,4.854; 19 -0.635,4.854; 20 -1.905,4.854; 21 -3.175,4.854; 22 -4.445,4.854; 23 -5.715,4.854; 24 -6.985,4.854
TQFP32-08 = smd 1.27 x 0.559: 1 -4.293,2.8; 2 -4.293,2; 3 -4.293,1.2; 4 -4.293,0.4; 5 -4.293,-0.4; 6 -4.293,-1.2; 7 -4.293,-2; 8 -4.293,-2.8; 17 4.293,-2.8; 18 4.293,-2; 19 4.293,-1.2; 20 4.293,-0.4; 21 4.293,0.4; 22 4.293,1.2; 23 4.293,2; 24 4.293,2.8 | smd 0.559 x 1.27: 9 -2.8,-4.293; 10 -2,-4.293; 11 -1.2,-4.293; 12 -0.4,-4.293; 13 0.4,-4.293; 14 1.2,-4.293; 15 2,-4.293; 16 2.8,-4.293; 25 2.8,4.293; 26 2,4.293; 27 1.2,4.293; 28 0.4,4.293; 29 -0.4,4.293; 30 -1.2,4.293; 31 -2,4.293; 32 -2.8,4.293
78XXS = drill 1.016 long: GND 0,-2.54; IN -2.54,-2.54; OUT 2.54,-2.54
1X02 = drill 1.016 long: 1 -1.27,0; 2 1.27,0
1X04/90 = drill 1.016 long: 1 -3.81,-3.81; 2 -1.27,-3.81; 3 1.27,-3.81; 4 3.81,-3.81
DO3316P = smd 2.92 x 2.79: 1 -5.28,0; 2 5.28,0
T0-46-A10XX = drill 0.7 pad 1.4 round: 1 -1.7,0; 2 1.7,0
P-LCC-2 = smd 4 x 2: A 0,1.798; C 0,-1.798
CTS406 = smd 1.9 x 1.4: 1 -2.2,-1.2; 2 2.2,-1.2; 3 2.2,1.2; 4 -2.2,1.2
R0805 = smd 1.3 x 1.5: 1 -0.95,0; 2 0.95,0
SKHMPXE010 = smd 1.6 x 1.4: 1 -4.2,2.25; 2 4.2,2.25; 3 -4.2,-2.25; 4 4.2,-2.25; 5 4.2,0
AL60P = drill 1.016 pad 2.54 octagon: 1 -3.251,0; 2 3.251,0
BMT1205XH7.5 = drill 0.9 pad 1.5 round: + 3.8,0; - -3.8,0
ML6 = drill 0.914 octagon: 1 -2.54,-1.27; 2 -2.54,1.27; 3 0,-1.27; 4 0,1.27; 5 2.54,-1.27; 6 2.54,1.27
SOT23 = smd 1 x 1.4: 1 -0.95,-1.1; 2 0.95,-1.1; 3 0,1.1
D-PAK_TO252AA = smd 1 x 1.6: 1 -2.28,-4.8; 3 2.28,-4.8 | smd 5.4 x 6.2: 4 0,2.5

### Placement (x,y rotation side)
C1  122,16.5 180 top
C2  179.75,22.5 90 top
C3  115,23.5 180 top
C4  124,5.75 90 top
C5  122,14.25 0 top
C6  199.5,61 270 top
C7  204.5,61 270 top
C8  188.75,60.75 90 top
C9  55,34 180 top
C10  184.25,39.5 180 top
C11  88,5 270 top
C12  104.75,15 270 top
C13  107.25,16 270 top
C14  214.5,30.5 180 top
C15  79.6,43 90 top
D1  194,51.75 90 top
D2  194,45 90 top
D3  215.5,17.5 90 top
D4  194,17.5 90 top
D5  155.5,17.5 90 top
D6  133.5,17 90 top
D7  133.5,45 90 top
D8  155.5,44.75 90 top
D9  121,42.22 0 top
D10  101.6,45.1 90 top
D11  73.5,45 90 top
D12  95,17.5 90 top
D13  73.5,17.5 90 top
D14  35,45 90 top
D15  35,38.45 90 top
D16  35,17.5 90 top
D17  35,23.75 90 top
D18  200,28 0 top
D19  130.75,5.25 0 top
D20  142.75,13.75 0 top
D21  208.5,63 270 top
D22  213.25,62.5 90 top
D23  121,50.29 0 top
IC1  175.5,43.5 90 top
IC2  55,43.5 90 top
IC3  114,17 0 top
IC4  202,54 180 top
JP1  150,13.75 180 top
JP2  55,22.7 270 top
JP3  61,22.7 270 top
JP4  49,22.7 270 top
L1  208.75,20 90 top
LDR  118.5,35 180 bottom
LED1  216.25,62.51 90 bottom
LED2  114.5,21 180 bottom
LED3  208.49,62.51 90 bottom
LED4  200.75,62.51 90 bottom
LED5  114.5,48.5 180 bottom
LED6  193.24,62.51 90 bottom
LED7  221.24,56.25 180 bottom
LED9  221.24,48.74 180 bottom
LED11  221.24,41.26 180 bottom
LED12  216.25,35 90 bottom
LED14  208.49,35 90 bottom
LED15  200.75,35 90 bottom
LED17  193.27,35 90 bottom
LED18  221.24,28.77 180 bottom
LED20  221.24,21.23 180 bottom
LED22  221.24,13.75 180 bottom
LED23  216.25,7.5 90 bottom
LED25  208.49,7.5 90 bottom
LED26  200.75,7.5 90 bottom
LED28  193.24,7.5 90 bottom
LED29  188.25,13.75 180 bottom
LED31  188.25,21.26 180 bottom
LED33  188.25,28.74 180 bottom
LED34  188.25,41.26 180 bottom
LED36  188.25,48.71 180 bottom
LED38  188.25,56.25 180 bottom
LED39  160.99,56.25 180 bottom
LED41  160.99,48.74 180 bottom
LED43  160.99,41.26 180 bottom
LED44  156,35 90 bottom
LED46  148.24,35 90 bottom
LED47  140.5,35 90 bottom
LED49  133.01,35 90 bottom
LED50  160.99,28.77 180 bottom
LED52  160.99,21.23 180 bottom
LED54  160.99,13.75 180 bottom
LED55  156,7.5 90 bottom
LED57  148.24,7.5 90 bottom
LED58  140.5,7.5 90 bottom
LED60  132.98,7.5 90 bottom
LED61  128,13.75 180 bottom
LED63  128,21.23 180 bottom
LED65  128,28.77 180 bottom
LED66  128,41.26 180 bottom
LED68  128,48.74 180 bottom
LED70  128,56.25 180 bottom
LED71  156,62.51 90 bottom
LED73  148.27,62.51 90 bottom
LED74  140.5,62.51 90 bottom
LED76  133.01,62.51 90 bottom
LED77  100.74,56.25 180 bottom
LED79  100.74,48.77 180 bottom
LED81  100.74,41.26 180 bottom
LED82  95.75,35 90 bottom
LED84  88.02,35 90 bottom
LED85  80.28,35 90 bottom
LED87  72.74,35 90 bottom
LED88  100.74,28.74 180 bottom
LED90  100.74,21.26 180 bottom
LED92  100.74,13.75 180 bottom
LED93  95.75,7.5 90 bottom
LED95  87.99,7.5 90 bottom
LED96  80.25,7.5 90 bottom
LED98  72.74,7.5 90 bottom
LED99  67.75,13.75 180 bottom
LED101  67.75,21.26 180 bottom
LED103  67.75,28.74 180 bottom
LED104  67.75,41.26 180 bottom
LED106  67.75,48.74 180 bottom
LED108  67.75,56.25 180 bottom
LED109  95.75,62.51 90 bottom
LED111  87.99,62.51 90 bottom
LED112  80.25,62.51 90 bottom
LED114  72.74,62.51 90 bottom
LED115  40.49,56.25 180 bottom
LED117  40.49,48.74 180 bottom
LED119  40.49,41.26 180 bottom
LED120  35.5,35 90 bottom
LED122  27.77,35 90 bottom
LED123  20,35 90 bottom
LED125  12.52,35.03 90 bottom
LED126  40.49,28.77 180 bottom
LED128  40.49,21.26 180 bottom
LED130  40.49,13.75 180 bottom
LED131  35.5,7.5 90 bottom
LED133  27.73,7.5 90 bottom
LED134  20,7.5 90 bottom
LED136  12.48,7.5 90 bottom
LED137  7.5,13.75 180 bottom
LED139  7.5,21.26 180 bottom
LED141  7.5,28.74 180 bottom
LED142  7.5,41.26 180 bottom
LED144  7.5,48.77 180 bottom
LED146  7.5,56.25 180 bottom
LED147  35.5,62.51 90 bottom
LED149  27.73,62.51 90 bottom
LED150  20,62.51 90 bottom
LED152  12.52,62.51 90 bottom
Q4  101.5,14.5 90 top
R1  176.25,30.25 180 top
R2  47,36.5 90 top
R3  106,4.25 90 top
R4  121,20.5 270 top
R5  123.25,20.5 90 top
R6  197.75,10.75 270 top
R7  201.25,11.75 0 top
R11  123.84,34.94 180 top
R12  90.5,5 270 top
R13  143,10.5 180 top
R14  98.25,6.75 0 top
R15  65.75,25 90 top
R16  68.5,23 270 top
S1  132.5,62 270 top
S2  114.5,62 270 top
S3  96.5,62 270 top
S4  78.5,62 270 top
S5  150.5,62 270 top
SP1  86,14 0 top
SP2  82.8,18.29 180 top
SV1  114.75,6 180 top
T1  93,8.5 90 top
T2  200,19.5 0 top

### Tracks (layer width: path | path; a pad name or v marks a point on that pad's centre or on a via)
!OE  (via drill 0.6)
  Top 0.406: IC2.21 51.92,40.33 52.5,39.75 v52.5,39.25 | IC3.14 115.2,10.3 v115.25,10.25 | v58.5,33.25 64.5,27.25 v120.75,27.25 | IC1.21 167.07,40.33 164,37.25 161.25,37.25 151.25,27.25 130.5,27.25 128.53,29.22 123.69,29.22 122.41,30.5 v120.75,30.5
  Bottom 0.406: v115.25,10.25 116,11 118.5,11 120.75,13.25 v120.75,27.25 v120.75,30.5 | v52.5,39.25 v58.5,33.25
!RESET  (via drill 0.6)
  Top 0.406: IC3.29 113.6,23.05 C3.2 114.05,24.55 114.75,25.25 v118,25.25 | SV1.5 110.14,5.2 R3.2
  Bottom 0.406: SV1.5 111,8.48 111,11.75 113.5,14.25 113.5,14.75 116.25,17.5 116.75,17.5 117.5,18.25 117.5,24.75 v118,25.25
+12V  (via drill 0.6)
  Top 0.406: R5.2 124.8,21.45 125.25,21 v125.25,18
  Top 0.813: v96.88,3.38 96.2,4.05 R12.2 C11.2
  Top 1.676: D18.C 196.5,28 192.5,24 187,24 182.96,19.96 C2.+
  Bottom 0.305: LED120.A 37.29,34.96 37.62,34.62
  Bottom 0.406: LED55.A 158,7.29 | 128.04,12 125.75,12 125.25,12.5 v125.25,18
  Bottom 0.813: LED5.A 114.5,39.46 113.28,39.46
  Bottom 1.676: LED119.A 40.5,37 38.5,35 38,35 37.62,34.62 37.5,34.5 | 98.5,35 LED82.A 99,35 101,37 101,39.21 LED81.A | LED44.A 158,35.25 161,38.25 LED43.A | LED12.A 219.5,35 221.24,36.74 LED11.A | LED11.A LED34.A 188.24,39.45 | LED137.A 7.45,12 | LED104.A 67.74,39.45 68.25,39.45 | LED92.A 100.74,9.24 99,7.5 LED93.A 97.5,7.45 97.5,4 v96.88,3.38 95.5,2 69.5,2 67.75,3.75 LED99.A 67.7,12 64.5,12 60.25,16.25 | LED55.A 159,7.5 161,9.5 LED54.A 163.95,11.95 169,17 | LED92.A 101.45,11.95 101.5,12 100.79,12 LED92.A | LED137.A 7.54,12 | 179.75,17 180,17 185,12 188.2,12 LED29.A 188.25,4.25 190.5,2 215.5,2 218,4.5 218,7.45 LED23.A 219.5,7.5 221.24,9.24 LED22.A 224.45,11.95 226.5,14 226.5,37.43 224.46,39.46 | 179.75,17 169,17 | LED61.A 128.04,12 128.04,3.96 130,2 156,2 158,4 158,7.29 | 169,17 166,20 166,37 163.5,39.5 | LED43.A 161.03,39.5 163.5,39.5 | LED2.A 108.05,19.2 106,21.25 106,38.13 104.66,39.46 | 45.5,44.4 45.5,60 43,62.5 37.31,62.5 LED147.A | LED109.A 102.5,62.5 106,59 106,40.7 | 163.5,39.5 166,42 166,59.5 163,62.5 157.81,62.5 LED71.A | LED11.A 224.46,39.46 | 224.46,39.46 226.5,41.5 226.5,58.5 222.5,62.5 LED1.A | 7.46,39.5 LED142.A 35.06,39.46 35.8,40.2 37.6,40.2 38.5,39.3 40.33,39.3 LED119.A | 179.75,17 C2.+ | 68.25,39.45 72.2,39.45 73.25,40.5 73.29,40.46 C15.+ 82.56,40.46 82.6,40.5 83.64,39.46 LED81.A | LED81.A 100.71,39.5 | 68.25,39.45 68.2,39.5 63.25,39.5 | LED43.A LED66.A 113.28,39.46 111.96,39.46 110.73,40.7 106,40.7 | 45.5,44.4 61.6,44.4 63.25,42.75 63.25,39.5 | 45.5,44.4 45.5,41.1 43.86,39.46 LED119.A | 63.3,39.4 63.3,19.3 60.25,16.25 | 63.3,39.4 63.3,39.6 | 60.25,16.25 60.2,16.2 | 63.25,39.5 63.25,39.45 63.3,39.4
  Bottom 1.676: 60.25,16.25 60,16.5 48,16.5 43.45,11.95 LED130.A 40.5,9.5 38.49,7.5 LED131.A 37.29,4.59 36.4,3.7 9.1,3.7 7.5,5.3 LED137.A | 104.66,39.46 105.9,40.7 106,40.7 | 104.66,39.46 LED81.A
+UB
  Top 1.016: D21.A D22.2
BUZ
  Top 0.406: IC3.9 111.25,12.66 111.25,11.75 110.25,10.75 107.75,10.75 103.75,6.75 R14.2
DCF
  Top 0.406: IC3.32 111.2,22.05 109.25,24 106.75,24 105.5,25.25 69,25.25 68.5,24.75 68.5,24.05 68.4,24.05 | 68.4,24.05 R15.1 65.72,24.02 JP3.2 | R16.1 68.4,23.95 68.4,24.05 | JP2.1 48.81,26.51 48.3,26 48.3,24.4 47.9,24 45.22,24 JP4.2
  Bottom 0.406: JP3.2 54.68,24.02 54.2,24.5 54.2,25.9 53.59,26.51 JP2.1
GND  (via drill 0.6)
  Top 0.406: IC3.5 107.35,16.6 C13.1 107.45,17 | IC3.21 119.15,17.4 119.75,18 121.75,18 | C1.1 122.5,16.3
  Top 0.61: IC1.1 180.35,35.6
  Bottom 0.61: 104.12,23.78 104.14,23.8 104.14,30.48 v104.12,30.48
  Bottom 1.27: 124.69,23.27 v124.69,23.37 124.69,30.73 | 104.12,23.78 v104.12,30.48 104.12,30.73
  Bottom 1.676: v75.87,23.5 v75.87,31.75 | v147.55,22 v147.55,31.75
  other vias: 179,34.25 115.25,14.25 116.75,16.5 109.75,12.5 111.55,16.6 111.5,14.25 113.5,16.5 118,13 180.75,34.25 177.25,34.25 180.75,31.5 170.25,31.5 173.25,40.25 174.5,39 57.25,38.25 57.25,36.25 52.75,37.75 54.75,40 60.25,34.25 50.25,34.5 50.25,32.75 52,33.5 124.69,30.48 104.12,23.88
  pour Top (isolate 0.254): 35,70 229,70 229,0 35.5,0 32,3.5 32,67
  pour Bottom: 108.75,17.75 108.75,11.75 117,11.75 119.25,11.75 119.25,16.5 119.25,17.75
  pour Bottom: 168.75,41.5 168.75,31 182,31 182,41.5
  pour Bottom: 48.25,41.5 48.25,31 61.5,31 61.5,41.5
LOCH1  (via drill 5.5 pad 10)
  other vias: 174.5,10
MISO
  Top 0.406: IC3.16 116.8,11.7 117.25,11.25 117.25,7.31 SV1.1
MOSI  (via drill 0.6)
  Top 0.406: 114.75,4.75 SV1.4 116,5.98 116,8 116.5,8.5 116.5,10.75 116,11.25 IC3.15 | IC1.2 178.28,37.78 174.25,33.75 162.5,33.75 153.5,24.75 128.75,24.75 127.25,26.25 v123.25,26.25
  Bottom 0.406: v123.25,26.25 123.25,11.5 120.75,9 117,9 116,8 116,5.98 SV1.4
N$1  (via drill 0.6)
  Top 0.406: v117.6,50.29 D23.C
  Bottom 0.406: v117.6,50.29 LED5.C
N$2
  Top 0.406: IC2.23 47,37.78 R2.2
N$3  (via drill 0.6)
  Top 0.406: IC1.23 172.97,37.78 v173,38 | v173,30.25 R1.2
  Bottom 0.61: v173,30.25 v173,38
N$4  (via drill 5.5 pad 10)
  other vias: 174.5,60
N$5
  Top 0.305: IC3.20 118.4,16.6 118.5,16.5
  Top 0.406: C1.2 120.45,16.5 120.35,16.6 IC3.20
N$6
  Top 0.305: IC3.23 120.45,19 R4.2 R5.1
N$7
  Top 0.254: C13.2 107.45,15 100.75,15 100.3,15.45 Q4.3
  Top 0.406: IC3.7 107.05,15 C13.2
N$8
  Top 0.305: 104.2,13.5 105.5,13.5 C12.2
  Top 0.406: 105.5,13.5 109.01,13.5 IC3.8 | 104.2,13.5 103.9,13.5 Q4.1
N$9
  Top 1.676: T2.4 200,22.25 202,24.25 202,27.8 D18.A 203.75,28 206.25,25.5 208.53,25.5 L1.2
N$10  (via drill 0.6)
  Top 0.305: IC3.24 118.05,19.8 118,19.75
  Top 0.406: 118,19.75 118.75,19.75 | IC3.24 118.5,20.01 v118.5,21.25 | R11.2 122.83,35 LDR.2
  Bottom 0.406: LDR.2 118.5,33.3 118.5,26.5 119,26 119,21.75 v118.5,21.25
N$11
  Top 0.61: 197.72,11.77 R6.1 197.75,11.75
  Top 1.27: 197.72,11.77 T2.1 | 197.75,11.75 R7.1
N$12
  Bottom 1.676: LED142.C LED144.A
N$13
  Top 0.61: SP1.2 86.6,16.65 SP2.-
  Top 0.813: R12.1 90.5,7.75 91.25,8.5 | 91.25,8.5 T1.3 | 91.25,8.5 90.5,9.25 90.5,12.75 SP1.2
N$14
  Bottom 1.676: LED20.C LED18.A
N$15
  Bottom 1.676: LED25.A LED23.C
N$16
  Bottom 1.676: LED4.A LED3.C
N$17
  Bottom 1.676: LED28.A LED26.C
N$18
  Bottom 1.676: LED17.A 198.5,35 LED15.C
N$19
  Bottom 1.676: LED14.A LED12.C | LED12.C
N$20
  Bottom 1.676: LED3.A LED1.C
N$21
  Bottom 1.676: LED15.A LED14.C
N$22
  Bottom 1.676: LED6.A LED4.C
N$23
  Bottom 1.676: LED9.C LED7.A
N$24  (via drill 0.6)
  Top 0.406: D3.A 215.5,19.5
  Top 0.813: 215.5,19.5 v217.5,19.5
  Bottom 0.406: v217.5,19.5 217.5,19.43
  Bottom 0.813: 217.5,19.43 LED20.A
N$25
  Bottom 1.676: LED36.C LED38.A
N$26
  Bottom 1.676: LED26.A LED25.C
N$27  (via drill 0.6)
  Top 0.406: D3.C 215.5,15.5
  Top 0.813: 215.5,15.5 v217.5,15.5
  Bottom 0.406: v217.5,15.5 217.5,15.55
  Bottom 0.813: 217.5,15.55 LED22.C
N$28
  Bottom 1.676: LED31.C LED33.A
N$29
  Bottom 1.676: LED41.C LED39.A
N$30
  Bottom 1.676: LED68.C LED70.A
N$31
  Top 0.813: C11.1 88,8.75 SP1.1
N$32
  Bottom 1.676: LED76.A LED74.C
N$33
  Bottom 1.676: LED73.A 153.5,62.51 153.5,62.5 LED71.C
N$34
  Bottom 1.676: LED49.A LED47.C
N$35
  Bottom 1.676: LED46.A LED44.C
N$36
  Top 0.813: JP1.2 D20.A 144.5,13.75 144.25,13.5 144.25,10.5 R13.1
N$37  (via drill 0.6)
  Top 0.406: D9.C 115.62,42.22 114.5,41.09 v114.5,36
  Bottom 0.813: LED2.C v114.5,36
N$38  (via drill 0.6)
  Top 0.406: D5.A 155.5,19.5
  Top 0.813: 155.5,19.5 v157.5,19.5
  Bottom 0.406: v157.5,19.5 157.5,19.43
  Bottom 0.813: 157.5,19.43 LED52.A
N$39  (via drill 0.6)
  Top 0.406: 194,15.5 D4.C
  Top 0.813: v192,15.5 194,15.5
  Bottom 0.406: 192,15.55 v192,15.5
  Bottom 0.813: LED29.C 192,15.55
N$40
  Bottom 1.676: LED60.A LED58.C
N$41
  Top 0.406: T1.1 95.45,7.55 95.75,7.25 95.75,7 96,6.75 R14.1
N$42
  Bottom 1.676: LED57.A LED55.C
N$43  (via drill 0.6)
  Top 0.406: D5.C 155.5,15.5
  Top 0.813: 155.5,15.5 v157.5,15.5
  Bottom 0.406: v157.5,15.5 157.5,15.55
  Bottom 0.813: 157.5,15.55 LED54.C
N$44  (via drill 0.6)
  Top 0.406: 194,19.5 D4.A
  Top 0.813: v192,19.5 194,19.5
  Bottom 0.406: 192,19.46 v192,19.5
  Bottom 0.813: LED31.A 192,19.46
N$45  (via drill 0.6)
  Top 0.406: 133.5,15 D6.C
  Top 0.813: v131.5,15 133.5,15
  Bottom 0.406: 131.5,15.05 v131.5,15
  Bottom 0.813: LED61.C 128,15.01 128,15 131.5,15.05
N$46  (via drill 0.6)
  Top 0.305: D19.C 128.5,5.25 128,4.75 | C4.1 124.05,4.75 | IC3.4 110.9,17.4 111.25,17.75 111.75,17.75 112.5,17 112.5,15.5 | IC3.6 109.71,15.75 111,15.75 111.25,15.5 112.5,15.5 | 112.5,15.5 116,15.5 116.5,15 IC3.18
  Top 0.406: IC3.18 119.5,15 120.25,14.25 C5.1 | R3.1 109.45,3.3 v109.5,3.25
  Top 0.813: 124.05,4.75 128,4.75 | C4.1 121.7,4.8 121.05,5.45 | 140.5,13.5 140.5,11.25 141.25,10.5 R13.2 | 140.5,13.7 D20.C | 140.5,13.7 140.5,13.75 | 140.5,13.5 140.5,13.7 | 140.5,13.5 140,13 136.5,13 135.5,12 135.5,9.5 133.75,7.75 130.25,7.75 128.5,6 128.5,5.3 D19.C | 121.05,5.45 C5.1 | SV1.2 120.33,4.73 121.05,5.45
  Bottom 0.406: v109.5,3.25 110.25,2.5 115.06,2.5 SV1.2
N$47
  Bottom 1.676: LED52.C LED50.A
N$48
  Bottom 1.676: LED63.C LED65.A
N$49
  Bottom 1.676: LED98.A LED96.C
N$50
  Bottom 1.676: LED95.A LED93.C
N$51
  Bottom 1.676: LED74.A LED73.C
N$52  (via drill 0.6)
  Top 0.61: D10.C 103.6,43.4 v104,43
  Bottom 0.61: v104,43 100.8,43 LED81.C
N$53  (via drill 0.6)
  Top 0.61: D10.A 103.8,46.8 v104,47
  Bottom 0.61: v104,47 100.77,47 LED79.A
N$54
  Bottom 1.676: LED87.A LED85.C
N$55
  Bottom 1.676: LED84.A LED82.C | LED82.C
N$56
  Bottom 1.676: LED47.A LED46.C
N$57
  Bottom 1.676: LED90.C LED88.A
N$58
  Bottom 1.676: LED101.C LED103.A
N$59
  Bottom 1.676: LED111.A 93.5,62.51 93.5,62.5 LED109.C
N$60
  Bottom 1.676: LED114.A LED112.C
N$61
  Bottom 1.676: LED58.A LED57.C
N$62
  Bottom 1.676: LED79.C LED77.A
N$63
  Bottom 1.676: LED106.C LED108.A
N$64
  Bottom 1.676: LED136.A LED134.C
N$65
  Bottom 1.676: LED133.A LED131.C
N$66  (via drill 0.6)
  Top 0.406: D15.C 36.35,36.75 36.7,37.1 36.7,38.25 v36.75,38.3
  Bottom 0.406: LED146.C 5.25,58.05 4.3,57.1 4.3,38.8 5.2,37.9 36.35,37.9 v36.75,38.3
N$67  (via drill 0.6)
  Top 0.406: D14.A 35,47
  Top 0.813: 35,47 v37,47
  Bottom 0.406: v37,47 37,46.94
  Bottom 0.813: 37,46.94 LED117.A
N$68
  Bottom 1.676: LED139.C LED141.A
N$69  (via drill 0.6)
  Top 0.406: 35,43 D14.C
  Top 0.813: 35,43 v37,43
  Bottom 0.406: v37,43 37,43.06
  Bottom 0.813: 37,43.06 LED119.C
N$70
  Bottom 1.676: LED128.C LED126.A
N$71
  Bottom 1.676: LED137.C LED139.A
N$72  (via drill 0.6)
  Top 0.406: D17.C 38.95,22.05 40.95,20.05 v40.95,5.8
  Bottom 0.406: LED141.C 5.04,30.54 4.4,29.9 4.4,5.2 7.6,2 37.3,2 40.95,5.65 v40.95,5.8
N$74
  Bottom 1.676: LED152.A LED150.C
N$75
  Bottom 1.676: LED149.A LED147.C
N$76  (via drill 0.6)
  Top 0.406: v194,48.5 D1.C
  Bottom 0.305: 221.5,58 221.25,58 221.24,58 LED7.C
  Bottom 0.406: v194,48.5 216.5,48.5 218,50 218,57.25 218.75,58 221.24,58
N$77
  Bottom 1.676: LED117.C LED115.A
N$78
  Bottom 1.676: LED144.C LED146.A
N$79
  Bottom 1.676: LED125.A 18.2,35.03 LED123.C
N$80
  Bottom 1.676: LED122.A LED120.C | LED120.C
N$81
  Top 0: 108.25,18.75 98.75,18.75 98.75,10.25 105,10.25 105,12.75
N$82
  Bottom 1.676: LED11.C LED9.A
N$83  (via drill 0.6)
  Top 0.406: IC3.12 113.6,11.1 112.5,10 108.5,10 v107,8.5 | v81.36,21.75 71.25,21.75 71.25,21.65 69.8,20.2 65.8,20.2 64.35,21.65 v60.76,21.65 | v96.5,11 99,8.5 v103.25,8.5 | JP3.1 54.96,26.56 54.2,25.8 54.2,24.5 53.7,24 51.22,24 JP2.2
  Bottom 0.406: v103.25,8.5 v107,8.5 | v81.36,21.75 86.25,21.75 96.5,11.5 v96.5,11 | v60.76,21.65 59.8,22.61 59.8,25.2 58.44,26.56 JP3.1
N$84
  Top 1.676: 213.25,65 221,65
N$86
  Bottom 1.676: LED112.A LED111.C
N$91
  Bottom 1.676: LED85.A LED84.C
N$96
  Bottom 1.676: LED96.A LED95.C
N$99  (via drill 0.6)
  Top 0.406: 73.5,47 D11.A
  Top 0.813: v71.5,47 73.5,47
  Bottom 0.406: 71,46.94 v71.5,47
  Bottom 0.813: LED106.A 71,46.94
N$101
  Top 0.406: IC1.22 170.59,39 167.5,39 164.75,36.25 161.75,36.25 152,26.5 129.75,26.5 128,28.25 65,28.25 62.5,30.75 62.5,36.75 61.47,37.78 IC2.2
N$104  (via drill 0.6)
  Top 0.406: 73.5,43 D11.C
  Top 0.813: v71.5,43 73.5,43
  Bottom 0.406: 71.5,43.06 v71.5,43
  Bottom 0.813: LED104.C 71.5,43.06
N$107  (via drill 0.6)
  Top 0.406: 194,43 D2.C
  Top 0.813: v192,43 194,43
  Bottom 0.406: 192,43.06 v192,43
  Bottom 0.813: LED34.C 192,43.06
N$108  (via drill 0.6)
  Top 0.406: 194,47 D2.A
  Top 0.813: v192,47 194,47
  Bottom 0.406: 191.5,46.91 v192,47
  Bottom 0.813: LED36.A 191.5,46.91
N$111  (via drill 0.6)
  Top 0.406: 133.5,19 D6.A
  Top 0.813: v131.5,19 133.5,19
  Bottom 0.406: 131.5,18.93 v131.5,19
  Bottom 0.813: LED63.A 128,19 128.07,18.93 131.5,18.93
N$112  (via drill 0.6)
  Top 0.61: D8.A 156.95,46.45 v157.5,47
  Bottom 0.61: v157.5,47 159.5,47
  Bottom 0.813: 159.5,47 LED41.A
N$113  (via drill 0.6)
  Top 0.61: D8.C 155.57,43 v157.5,43
  Bottom 0.61: LED43.C 160.93,43 v157.5,43
N$114  (via drill 0.6)
  Top 0.406: 133.5,43 D7.C
  Top 0.813: v131.5,43 133.5,43
  Bottom 0.406: 131.5,43.06 v131.5,43
  Bottom 0.813: LED66.C 131.5,43.06
N$115  (via drill 0.6)
  Top 0.406: 133.5,47 D7.A
  Top 0.813: v131.5,47 133.5,47
  Bottom 0.406: 131.5,46.94 v131.5,47
  Bottom 0.813: LED68.A 131.5,46.94
N$116  (via drill 0.6)
  Top 0.406: 73,19.5 D13.A
  Top 0.813: v71.5,19.5 73,19.5
  Bottom 0.406: 71,19.46 v71.5,19.5
  Bottom 0.813: LED101.A 71,19.46
N$117  (via drill 0.6)
  Top 0.406: 73,15.5 D13.C
  Top 0.813: v71.5,15.5 73,15.5
  Bottom 0.406: 71,15.55 v71.5,15.5
  Bottom 0.813: LED99.C 71,15.55
N$118  (via drill 0.6)
  Top 0.406: D12.A 95,19.5
  Top 0.813: 95,19.5 v97,19.5
  Bottom 0.406: v97,19.5 97,19.46
  Bottom 0.813: 97,19.46 LED90.A
N$119  (via drill 0.6)
  Top 0.406: D12.C 95,15.5
  Top 0.813: 95,15.5 v97,15.5
  Bottom 0.406: v97,15.5 97,15.55
  Bottom 0.813: 97,15.55 LED92.C
N$120  (via drill 0.6)
  Top 0.406: D16.A 35,19.5
  Top 0.813: 35,19.5 v37,19.5
  Bottom 0.406: v37,19.5 37,19.46
  Bottom 0.813: 37,19.46 LED128.A
N$121
  Bottom 1.676: LED150.A LED149.C
N$122  (via drill 0.6)
  Top 0.406: D16.C 35,15.5
  Top 0.813: 35,15.5 v37,15.5
  Bottom 0.406: v37,15.5 37,15.55
  Bottom 0.813: 37,15.55 LED130.C
N$126
  Bottom 1.676: LED123.A LED122.C
N$131
  Bottom 1.676: LED134.A LED133.C
N$147  (via drill 5.5 pad 10)
  other vias: 54,9.5
N$152  (via drill 5.5 pad 10)
  other vias: 54,60
PWM  (via drill 0.6)
  Top 0.406: IC3.13 114.4,10.65 113,9.25 110.5,9.25 v109.5,8.25 | v108,1.75 108.25,1.5 195.75,1.5 198,3.75 198,9.7 R6.2
  Bottom 0.406: v108,1.75 108,6.75 v109.5,8.25
SCK  (via drill 0.6)
  Top 0.406: SV1.3 114.75,7.25 | IC2.3 61.45,39.05 63.5,37 63.5,31.5 65.75,29.25 v122,29.25 | IC1.3 178.06,39.05 174,35 162.25,35 153,25.75 129,25.75 127.5,27.25 v122,27.25 | IC3.17 119.3,14.2 119.5,14 v119.5,10.5
  Bottom 0.406: SV1.3 114.75,8.25 116.5,10 119,10 v119.5,10.5 122,13 v122,27.25 v122,29.25
SEG1_A  (via drill 0.6)
  Top 0.406: IC1.5 178.16,41.59 177.25,42.5 177.25,50.8 v176.33,51.72
  Bottom 0.305: 191.43,62.5 LED6.C
  Bottom 0.406: 191.43,62.5 188,62.5 178.4,52.9 177.51,52.9 v176.33,51.72
SEG1_B  (via drill 0.6)
  Top 0.406: IC1.6 178.63,42.87 178,43.5 178,51.29 v178.25,51.54
  Bottom 0.305: 188.2,58 LED38.C
  Bottom 0.406: 188.2,58 185.7,58 185.5,58 184.71,58 v178.25,51.54
SEG1_C  (via drill 0.6)
  Top 0.406: IC1.7 183.12,44.13 v183.5,43.75
  Bottom 0.406: LED33.C 188.25,34.25 187,35.5 185.5,35.5 183.5,37.5 v183.5,43.75
SEG1_D  (via drill 0.6)
  Top 0.406: v192,29 190,31 190,40.25 189.25,41 189.25,44.25 188.09,45.41 IC1.8
  Bottom 0.406: LED28.C 191.44,10.94 194,13.5 194,27 v192,29
SEG1_E  (via drill 0.6)
  Top 0.406: v192,31 192,40.25 190.5,41.75 190.5,45 188.82,46.67 IC1.9
  Bottom 0.406: 221.5,31 221.5,30.83 221.34,30.66 LED18.C 221.17,30.5 221,30.5 219.25,32.25 210.5,32.25 209.25,31 v192,31
SEG1_F
  Top 0.406: IC1.10 189.94,47.95 191.75,49.75 191.75,53 192.25,53.5 193.95,53.5 D1.A
SEG1_G  (via drill 0.6)
  Top 0.406: IC1.11 182.22,49.22 v182.5,49.5
  Bottom 0.406: v182.5,49.5 183.5,49.5 185,48 185,37.75 186,36.75 191.5,36.75 191.5,35.03 LED17.C
SEG2_A  (via drill 0.6)
  Top 0.406: IC1.13 162.51,50.48 157,56 v156,56
  Bottom 0.406: LED76.C 131.5,62.23 131.5,60 135.5,56 v156,56
SEG2_B  (via drill 0.6)
  Top 0.406: IC1.14 160.78,49.22 v156,54
  Bottom 0.406: LED70.C 128.95,58.05 129.5,57.5 130.5,57.5 134,54 v156,54
SEG2_C  (via drill 0.6)
  Top 0.406: IC1.15 166.69,47.95 149,30.25 v131.75,30.25
  Bottom 0.406: LED65.C 128.06,30.5 128.5,30 129,30.5 131.5,30.5 v131.75,30.25
SEG2_D  (via drill 0.6)
  Top 0.406: IC1.16 166.93,46.67 149.5,29.25 136.25,29.25 v135.5,28.5
  Bottom 0.406: LED60.C 131.19,9.69 135.5,14 v135.5,28.5
SEG2_DPO  (via drill 0.6)
  Top 0.406: D23.A 123.95,50.29 124.21,50.55 124.21,51.82 v123.44,52.58 | 180.85,50.48 IC1.12 180.35,53.12 179.55,53.93 v177.85,53.93
  Bottom 0.406: v123.44,52.58 123.44,61.21 127.43,65.2 162.9,65.2 167.8,60.3 167.8,55.3 169.17,53.93 v177.85,53.93
SEG2_DPU  (via drill 0.6)
  Top 0.406: IC1.20 172.59,41.59 174,43 174,51.5 172.5,53 168.25,53 166.25,55 166.25,57.95 163.85,60.35 v160.85,60.35 | D9.A 124.51,42.22 125.44,41.3 v136.22,41.3
  Bottom 0.406: v160.85,60.35 160.2,59.7 158.8,59.7 157.5,58.4 157.5,50.6 155.9,49 154.4,49 152.7,47.3 152.7,42.4 151.6,41.3 v136.22,41.3
SEG2_E  (via drill 0.6)
  Top 0.406: IC1.17 168.41,45.41 v168,45 | v164,30.5 v168,30.5
  Bottom 0.406: v164,30.5 160.92,30.5 LED50.C | v168,30.5 v168,45
SEG2_F  (via drill 0.6)
  Top 0.406: IC1.18 172.63,44.13 173.25,44.75 173.25,51 172.5,51.75 167.25,51.75 165,54 165,57 v164,58
  Bottom 0.406: LED39.C 163.95,58.05 v164,58
SEG2_G  (via drill 0.6)
  Top 0.406: IC1.19 167.87,42.87 163.5,38.5 160.75,38.5 150.5,28.25 v137.5,28.25
  Bottom 0.406: LED49.C 131.22,32.53 131.75,32 136.25,32 137.5,30.75 v137.5,28.25
SEG3_A  (via drill 0.6)
  Top 0.406: IC2.5 57.41,41.59 56.5,42.5 56.5,52 v60.5,56
  Bottom 0.406: v60.5,56 67,62.5 70.93,62.5 LED114.C
SEG3_B  (via drill 0.6)
  Top 0.406: IC2.6 58.13,42.87 57.5,43.5 57.5,50.75 v61,54.25
  Bottom 0.406: v61,54.25 64.75,58 67.7,58 LED108.C
SEG3_C  (via drill 0.6)
  Top 0.406: IC2.7 61.37,44.13 64.5,41 64.5,33.5 v65.25,32.75
  Bottom 0.406: LED103.C 68,30.79 68,32 67.25,32.75 v65.25,32.75
SEG3_D  (via drill 0.6)
  Top 0.406: IC2.8 61.84,45.41 65.5,41.75 65.5,34.25 69.25,30.5 v72,30.5
  Bottom 0.406: LED98.C 70.93,11.43 73,13.5 73,28 72,29 v72,30.5
SEG3_E  (via drill 0.6)
  Top 0.406: v97.25,31.25 96.25,30.25 74.75,30.25 73.25,31.75 69.75,31.75 66.25,35.25 66.25,42.45 62.02,46.67 IC2.9
  Bottom 0.406: 101,30.8 LED88.C 100.28,31 97.5,31 v97.25,31.25
SEG3_F  (via drill 0.6)
  Top 0.406: IC2.10 63.6,47.95 v63.65,47.9
  Bottom 0.406: LED77.C 100.69,58 72.4,58 70.7,56.3 65.8,56.3 63.65,54.15 v63.65,47.9
SEG3_G  (via drill 0.6)
  Top 0.406: IC2.11 64.28,49.22 65.5,48 65.5,44.7 67.9,42.3 v67.9,36.85
  Bottom 0.406: 70.94,36.75 LED87.C 70.84,34.9 68.7,34.9 67.9,35.7 v67.9,36.85
SEG4_A  (via drill 0.6)
  Top 0.406: IC2.13 40.31,50.48 35.4,55.4 v35.4,66
  Bottom 0.406: LED152.C 10.75,62.48 10.75,65 11.75,66 v35.4,66
SEG4_B
  Top 0.406: IC2.14 45.31,49.22 36.25,40.15 D15.A
SEG4_C
  Top 0.406: D17.A 35,27 34,28 34,32.3 38.5,36.8 38.5,41.25 45.2,47.95 IC2.15
SEG4_D  (via drill 0.6)
  Top 0.406: IC2.16 45.17,46.67 39.5,41 39.5,36 35,31.5 v35,29
  Bottom 0.406: LED136.C 10.69,10.19 11.25,10.75 34,10.75 35,11.75 v35,29
SEG4_E  (via drill 0.6)
  Top 0.406: IC2.17 45.16,45.41 40.5,40.75 v40.5,34
  Bottom 0.406: LED126.C v40.5,34
SEG4_F  (via drill 0.6)
  Top 0.406: v36.5,58 36.5,56.25 41.25,51.5 51.75,51.5 52.75,50.5 52.75,44.75 52.13,44.13 IC2.18
  Bottom 0.406: LED115.C 36.55,58.05 v36.5,58
SEG4_G  (via drill 0.6)
  Top 0.406: IC2.19 43.97,42.87 41.6,40.5 41.6,33.4 39.7,31.5 v37,31.5
  Bottom 0.406: LED125.C 10.72,32.28 11.5,31.5 v37,31.5
TAS_1  (via drill 0.6)
  Top 0.406: S1.3 S1.4 130.25,56.25 129.5,55.5 112.25,55.5 110.5,53.75 v110.5,36.75 | IC3.30 112.8,22.95 v111.5,24.25
  Bottom 0.406: v110.5,36.75 110.5,25.25 v111.5,24.25
TAS_2  (via drill 0.6)
  Top 0.406: S2.3 S2.4 112.25,57 109.5,54.25 v109.5,37.5 | IC3.1 109.2,19.8 108.75,20.25 v108.75,21.25
  Bottom 0.406: v108.75,21.25 109.5,22 v109.5,37.5
TAS_3  (via drill 0.6)
  Top 0.406: IC3.2 108.75,19 107.5,20.25 v107.5,22 | S3.3 S3.4 94.25,56.5 94.75,56 106.75,56 108.5,54.25 v108.5,38.25
  Bottom 0.406: v108.5,38.25 108.5,23.25 107.5,22.25 v107.5,22
TAS_4  (via drill 0.6)
  Top 0.406: IC3.31 112,22.25 109.25,25 v107.5,25 | S4.3 S4.4 76.25,56 77.25,55 106.25,55 107.5,53.75 v107.5,39
  Bottom 0.406: v107.5,25 v107.5,39
TAS_5  (via drill 0.6)
  Top 0.406: S5.3 S5.4 148.25,55.75 147,54.5 112.75,54.5 111.5,53.25 v111.5,37.5 | IC3.11 112.8,11.8 v112,11
  Bottom 0.406: v112,11 112.75,11.75 118,11.75 120,13.75 120,26.25 119.5,26.75 119.5,31.75 122,34.25 122,35.75 120.25,37.5 v111.5,37.5
V+
  Top 0.61: IC4.IN 204.5,56.54 C7.2
  Top 1.016: D21.K 208.5,56.5 208.75,56.5 208.75,56.54
  Top 1.422: L1.1 208.75,18 217,26.25 | 204.5,56.54 208.75,56.54 213.46,56.54 217,53 217,26.25 | 217,26.25 217.04,26.29 C14.+
VCC  (via drill 0.6)
  Top 0.406: JP2.4 49.81,18.89 | JP2.4 52.24,18.94 | JP2.4 51.1,18.8 | JP4.3 47.87,21.43 48.3,21 48.3,19.5 48.91,18.89 JP2.4
  Top 0.61: IC1.24 174.01,36.52 177,39.5 | 183.25,39.5 182.43,40.33 IC1.4 177.82,40.33 177,39.5 | 183.25,39.5 183.5,39.25 | v176,40.5 177,39.5 | 188.79,56.54 188.79,57.56 C8.+ | 183.25,39.5 C10.2 183.5,39.7 183.5,41 184.25,41.75 186.25,41.75 187,41 187,34.25 185.5,32.75 163.25,32.75 154.25,23.75 v137.5,23.75 128,23.75 127,24.75 122.75,24.75 121.25,26.25 v116.75,26.25 v79.16,26.25 68.75,26.25 68.45,25.95 R15.2 64.05,25.95 59.25,30.75 55.25,30.75 54.05,31.95 C9.2 54.05,35.95 53.5,36.5 | 53.5,36.5 50.16,36.5 IC2.24 | IC2.4 57.33,40.33 53.5,36.5 | IC4.OUT 199.5,56.54 C6.2 | JP3.4 61.16,18.94 66.4,13.7 75.7,13.7 79,17 SP2.+
  Top 0.813: D19.A 135,5.25 137.5,7.75 v137.5,11
  Top 1.422: IC4.OUT 188.79,56.54 v183.75,51.5
  Bottom 0.406: LDR.1 116.8,26.25 v116.75,26.25 | JP3.4 JP2.4
  Bottom 0.61: SP2.+ 79.16,18.44 v79.16,26.25
  Bottom 0.813: v137.5,23.75 v137.5,11
  Bottom 1.422: v183.75,51.5 181,51.5 176,46.5 v176,40.5
(copper drawn outside any net)
  shapes: Top area x1

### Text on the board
Top: www.ulrichradig.de / FIFI 2012
tPlace: CON | REI | POL
bPlace: MIN / - | STD / + | SET | DISP | ALARM | SEG3 | SEG2 | SEG1 | SEG4
tNames: +
tStop: www.ulrichradig.de / FIFI 2012
bStop: MIN / - | STD / + | SET | DISP | ALARM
